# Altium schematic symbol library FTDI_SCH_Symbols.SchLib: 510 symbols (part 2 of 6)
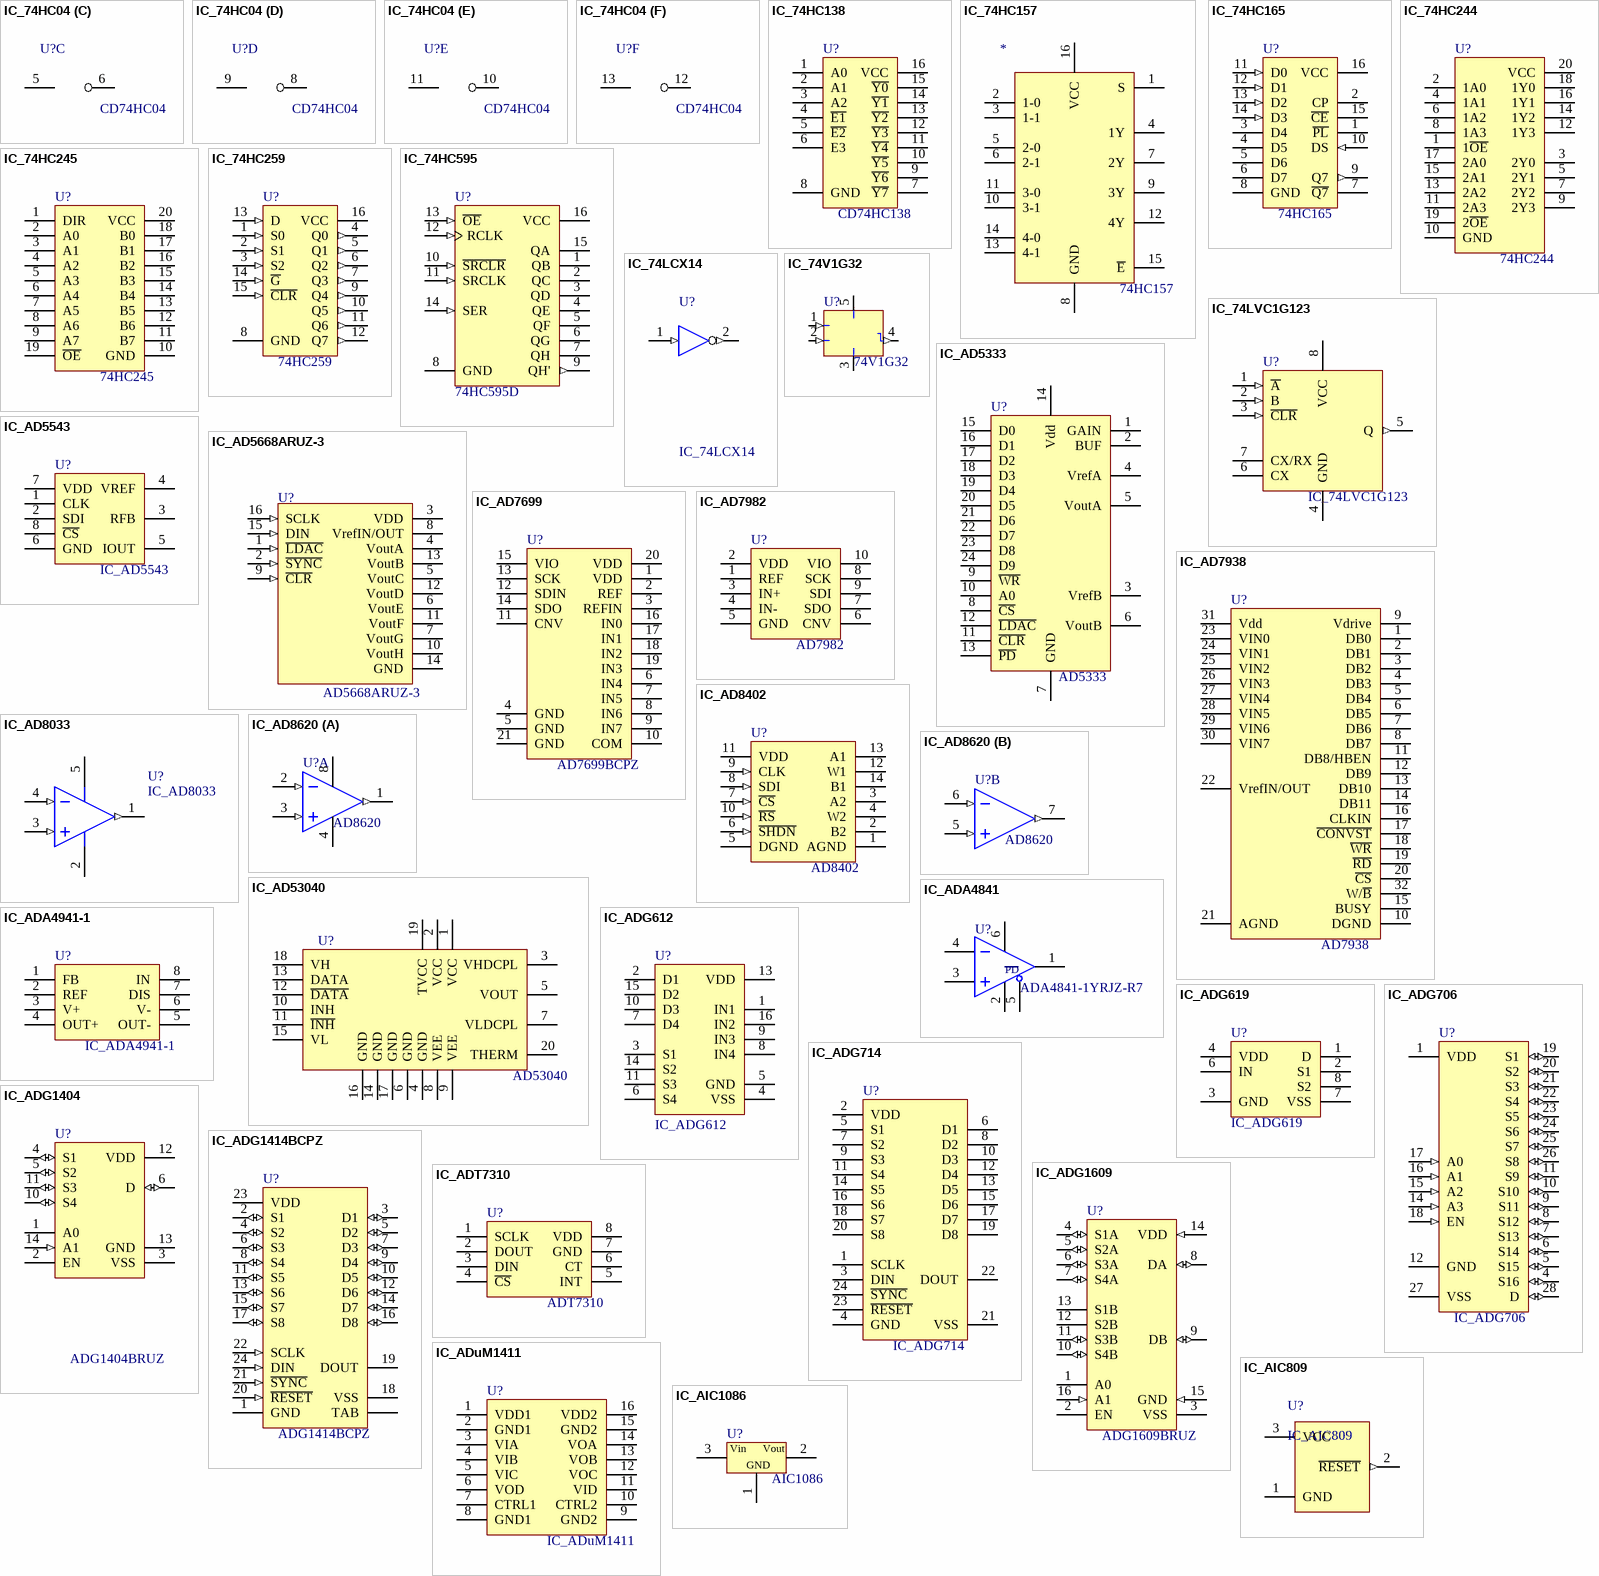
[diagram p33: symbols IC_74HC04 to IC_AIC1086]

## IC_ADG1404
designator U?, comment ADG1404BRUZ
1.5 Ohm On Resistance,  ±15 V/12 V/±5 V, 4:1, iCMOS Multiplexer
footprint TSOP65P640X110-14N (TSOP, 14-Leads, Body 5.1x4.5mm (max), Pitch 0.65mm, IPC Medium Density)
pins: 1 A0 (power), 2 EN, 3 VSS, 4 S1 (io), 5 S2 (io), 6 D (io), 7 NC (io) hidden, 8 NC (io) hidden, 9 NC (io) hidden, 10 S4 (io), 11 S3 (io), 12 VDD (power), 13 GND, 14 A1 (in)

## IC_ADG1414BCPZ
designator U?, comment ADG1414BCPZ
9.5 Ohm RON ±15 V/+12 V/±5 V iCMOS Serially-Controlled Octal SPST Switches
footprint QFN50P400X400X100-24N (QFN, 24-Leads, Body 4.1x4.1mm (max), Pitch 0.50mm, IPC Medium Density)
pins: 1 GND (power), 2 S1 (io), 3 D1 (io), 4 S2 (io), 5 D2 (io), 6 S3 (io), 7 D3 (io), 8 S4 (io), 9 D4 (io), 10 D5 (io), 11 S5 (io), 12 D6 (io), 13 S6 (io), 14 D7 (io), 15 S7 (io), 16 D8 (io), 17 S8 (io), 18 VSS (power), 19 DOUT (oc), 20 ~{RESET} (in), 21 ~{SYNC} (in), 22 SCLK (in), 23 VDD (power), 24 DIN (in), 25 TAB (power)

## IC_ADG1609
designator U?, comment ADG1609BRUZ
4.5 Ohm RON, 4-/8-Channel  ±5 V,+12 V, +5 V, and +3.3 V Multiplexers
footprint TSSOP65P640X110_HS-16N (TSOP, 16-Leads, Body 5.1x4.5mm (max), Pitch 0.65mm, IPC Medium Density)
pins: 1 A0 (power), 2 EN, 3 VSS, 4 S1A (io), 5 S2A (io), 6 S3A (io), 7 S4A (io), 8 DA (io), 9 DB (io), 10 S4B (io), 11 S3B (io), 12 S2B (power), 13 S1B, 14 VDD (in), 15 GND (in), 16 A1 (in)

## IC_ADT7310
designator U?, comment ADT7310
IC TEMP SENS 16B DGTL SPI 8SOIC; Manufacturer: Analog Devices Inc; ManufacturerPartNo: ADT7310TRZ-REEL7
signal-integrity model Connector
footprint SOIC127P600X300-8N (SOIC, 8-Leads, Body 4.9x3.9mm (max), Pitch 1.27mm, IPC Medium Density)
pins: 1 SCLK, 2 DOUT, 3 DIN, 4 ~{CS}, 5 INT, 6 CT, 7 GND, 8 VDD

## IC_ADuM1411
designator U?
Quad-Channel Digital Isolator
footprint SOICW-16_N (SOIC-Wide, 16-Leads, Body 12.8x7.5mm, Pitch 1.27mm, IPC Medium Density)
pins: 1 VDD1, 2 GND1, 3 VIA, 4 VIB, 5 VIC, 6 VOD, 7 CTRL1, 8 GND1, 9 GND2, 10 CTRL2, 11 VID, 12 VOC, 13 VOB, 14 VOA, 15 GND2, 16 VDD2

## IC_AIC809
designator U?
3-Pin Microprocessor Reset Circuit; Analog Integrations Corporation
footprint SOT23-3AL (SOT23 SMT Package)
pins: 1 GND (power), 2 ~{RESET} (out), 3 VCC (power)

## IC_AIC1086
designator U?, comment AIC1086
1.5A Low Dropout Positive Voltage Regulator
footprint TO252P990X238-3N (D-PAK, 3-Pads, Body 6.2x6.7mm (max), IPC Medium Density)
footprint SOT223P700X180-4N (SOT223, 4-Leads, Body 6.7x7.3mm (max), Pitch 2.30mm, IPC Medium Density)
pins: 1 GND (power), 2 Vout (power), 3 Vin (power)

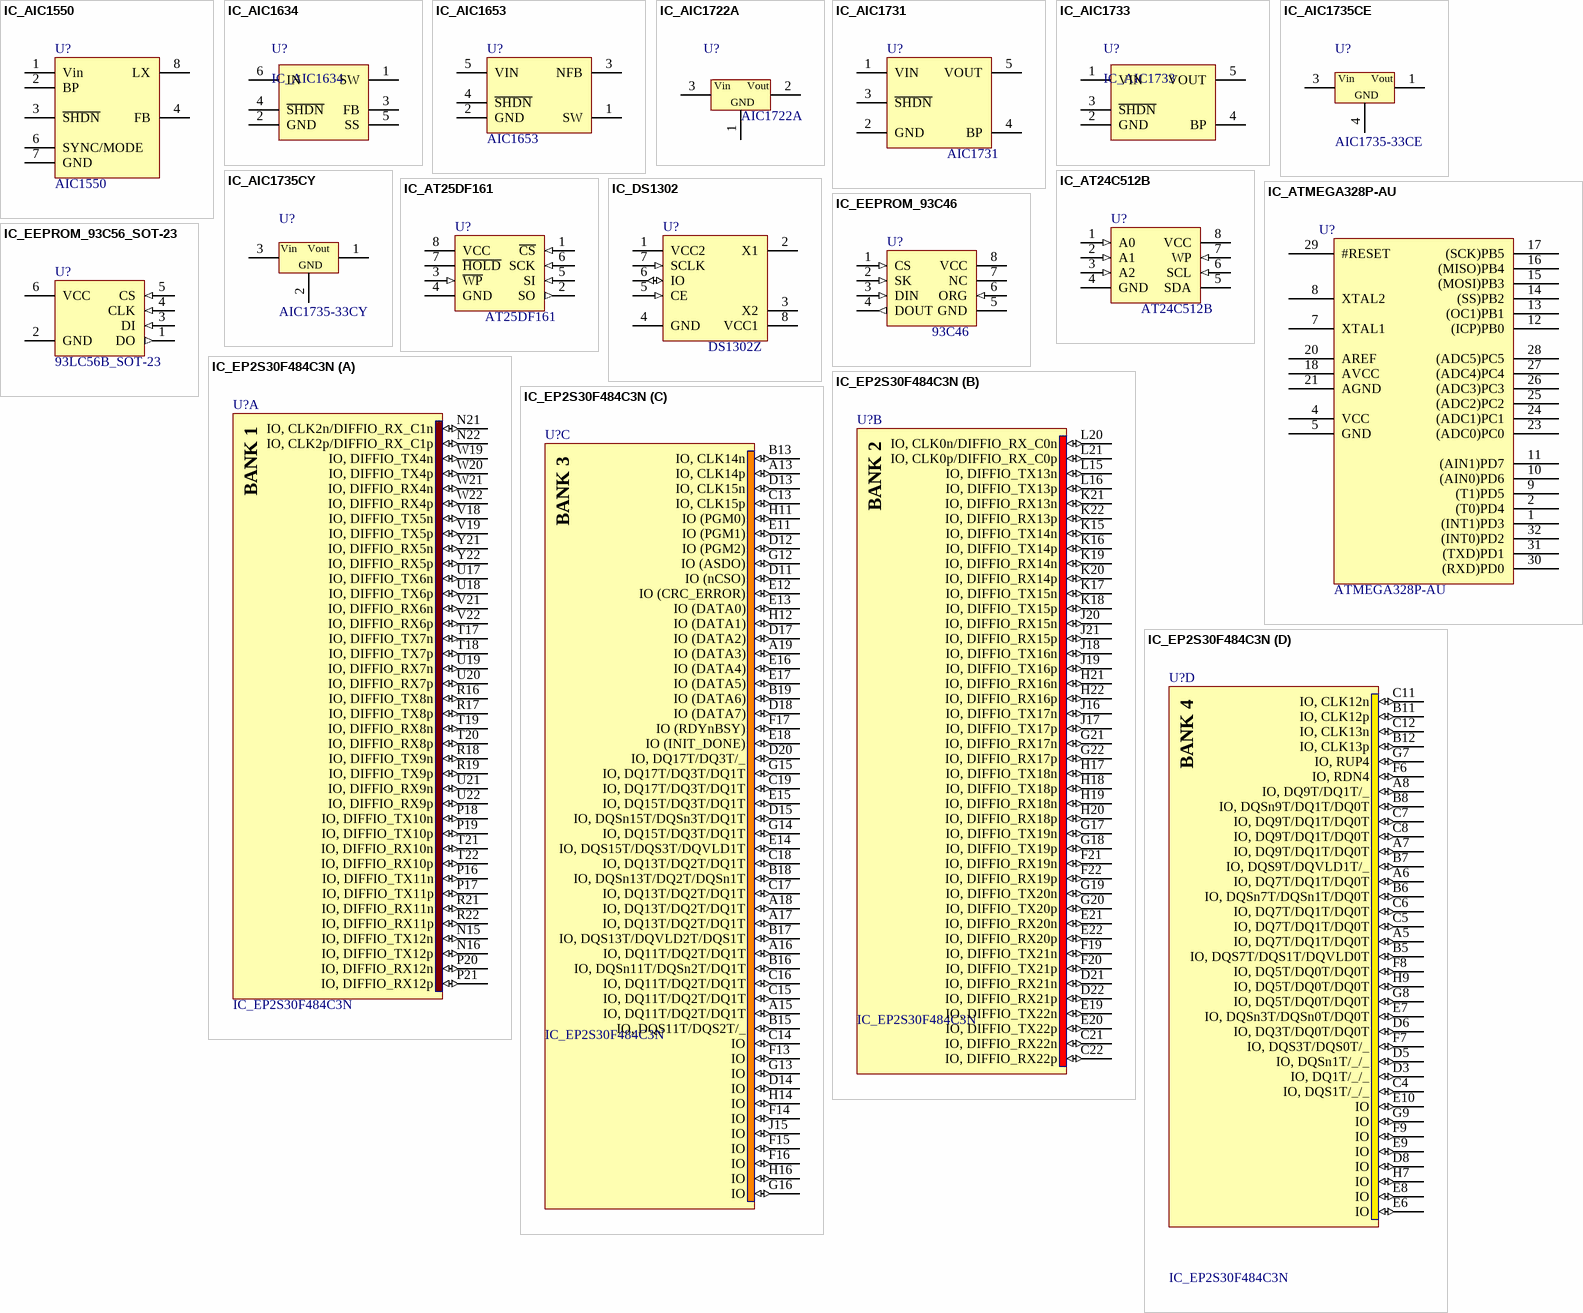
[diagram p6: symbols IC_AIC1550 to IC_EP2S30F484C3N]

## IC_AIC1550
designator U?, comment AIC1550
Low-Noise Synchronous PWM Step-Down  DC/DC Converter
footprint MSOP-08
pins: 1 Vin, 2 BP, 3 ~{SHDN}, 4 FB, 5 RT hidden, 6 SYNC/MODE, 7 GND, 8 LX

## IC_AIC1634
designator U?
1.4MHz Current-Mode, PWM Step-Up Converter
footprint SOT23-6N (SOT23, 6-Leads, Body 3.0x3.0mm (max), Pitch 0.95mm, IPC Medium Density)
pins: 1 SW, 2 GND, 3 FB, 4 ~{SHDN}, 5 SS, 6 IN

## IC_AIC1653
designator U?, comment AIC1653
Micropower Inverting DC/DC Converter in SOT-23-5
footprint SOT23-5AL (SOT23, 5-Leads, Body 2.9x1.6mm, Pitch 0.95mm, Lead Span 2.8mm)
pins: 1 SW, 2 GND, 3 NFB, 4 ~{SHDN}, 5 VIN

## IC_AIC1722A
designator U?, comment AIC1722A
300mA Low Dropout Linear Voltage Regulator; Analog Integration Corporation
footprint SOT23-3AL (SOT23 SMT Package)
pins: 1 GND (power), 2 VOUT (power), 3 VIN (power)

## IC_AIC1731
designator U?, comment AIC1731
300mA, Low Dropout Linear Regulator  with Shutdown
footprint SOT23-5AL (SOT23, 5-Leads, Body 2.9x1.6mm, Pitch 0.95mm, Lead Span 2.8mm)
pins: 1 VIN, 2 GND, 3 ~{SHDN}, 4 BP, 5 VOUT

## IC_AIC1733
designator U?
500mA, Low Dropout Linear Regulator  with Shutdown
footprint SOT23-5AL (SOT23, 5-Leads, Body 2.9x1.6mm, Pitch 0.95mm, Lead Span 2.8mm)
pins: 1 VIN, 2 GND, 3 ~{SHDN}, 4 BP, 5 VOUT

## IC_AIC1735CE
designator U?, comment AIC1735-33CE
0.5A; Vlotage Regulator; TO252
footprint TO252P990X238-3N (D-PAK, 3-Pads, Body 6.2x6.7mm (max), IPC Medium Density)
pins: 1 Vout (power), 3 Vin (power), 4 GND (power)

## IC_AIC1735CY
designator U?, comment AIC1735-33CY
0.5A; Vlotage Regulator; SOT223
footprint SOT223P700X180-4N (SOT223, 4-Leads, Body 6.7x7.3mm (max), Pitch 2.30mm, IPC Medium Density)
pins: 1 Vout (power), 2 GND (power), 3 Vin (power), 4 GND (power) hidden to GND

## IC_AT24C512B
designator U?, comment AT24C512B
Two-wire Serial  EEPROM  512K (65,536 x 8)
pins: 1 A0 (in), 2 A1 (in), 3 A2 (in), 4 GND (power), 5 SDA (oc), 6 SCL (in), 7 WP (in), 8 VCC (power)

## IC_AT25DF161
designator U?, comment AT25DF161
16-Megabit  2.3V or 2.7V  Minimum  SPI Serial Flash  Memory; Atmel
footprint SO-8N (8-Pin Small Outline Integrated Circuit 1.27 mm Pitch, IPC Medium Density)
pins: 1 ~{CS} (in), 2 SO (out), 3 ~{WP} (in), 4 GND (power), 5 SI (in), 6 SCK (in), 7 ~{HOLD}, 8 VCC (power)

## IC_ATMEGA328P-AU
designator U?, comment ATMEGA328P-AU
pins: 1 (INT1)PD3, 2 (T0)PD4, 4 VCC, 5 GND, 7 XTAL1, 8 XTAL2, 9 (T1)PD5, 10 (AIN0)PD6, 11 (AIN1)PD7, 12 (ICP)PB0, 13 (OC1)PB1, 14 (SS)PB2, 15 (MOSI)PB3, 16 (MISO)PB4, 17 (SCK)PB5, 18 AVCC, 20 AREF, 21 AGND, 23 (ADC0)PC0, 24 (ADC1)PC1, 25 (ADC2)PC2, 26 (ADC3)PC3, 27 (ADC4)PC4, 28 (ADC5)PC5, 29 #RESET, 30 (RXD)PD0, 31 (TXD)PD1, 32 (INT0)PD2

## IC_DS1302
designator U?, comment DS1302Z
Trickle-Charge Timekeeping Chip
footprint SO-8N (8-Pin Small Outline Integrated Circuit 1.27 mm Pitch, IPC Medium Density)
pins: 1 VCC2 (power), 2 X1, 3 X2, 4 GND (power), 5 CE (in), 6 IO (io), 7 SCLK (in), 8 VCC1 (power)

## IC_EEPROM_93C46
designator U?, comment 93C46
Serial interface EEPROM
footprint SO-8_N (8-Pin Small Outline Integrated Circuit 1.27 mm Pitch, IPC Medium Density)
footprint TSSOP-8 (Shrink Small Outline; 8 Leads; Body Width 4.4 mm; Pitch 0.65 mm)
pins: 1 CS (in), 2 SK (in), 3 DIN (in), 4 DOUT (out), 5 GND (power), 6 ORG (in), 7 NC, 8 VCC (power)

## IC_EEPROM_93C56_SOT-23
designator U?, comment 93LC56B_SOT-23
Serial interface EEPROM in SOT-23 package
footprint SOT23-6N (SOT23, 6-Leads, Body 3.0x3.0mm (max), Pitch 0.95mm, IPC Medium Density)
pins: 1 DO (out), 2 GND (power), 3 DI (in), 4 CLK (in), 5 CS (in), 6 VCC (power)

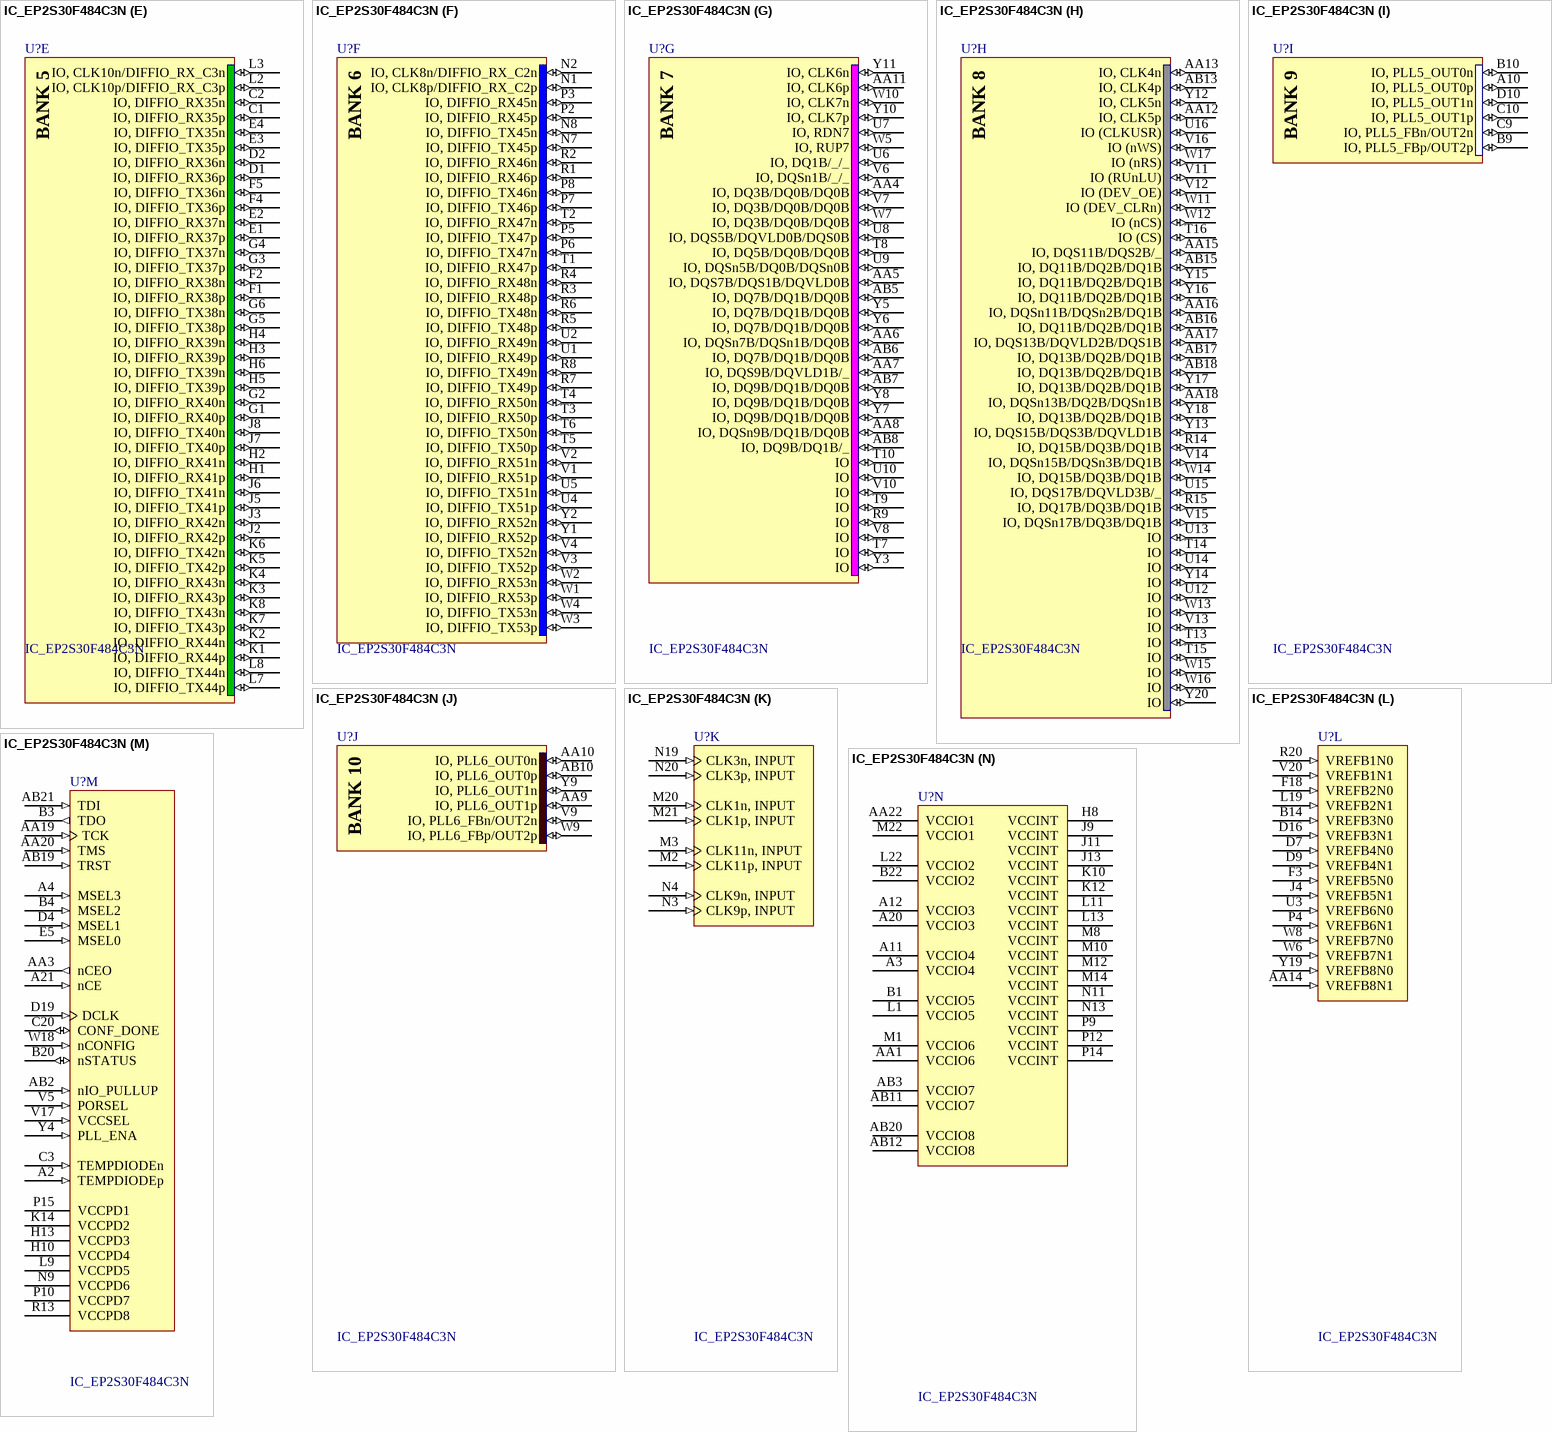
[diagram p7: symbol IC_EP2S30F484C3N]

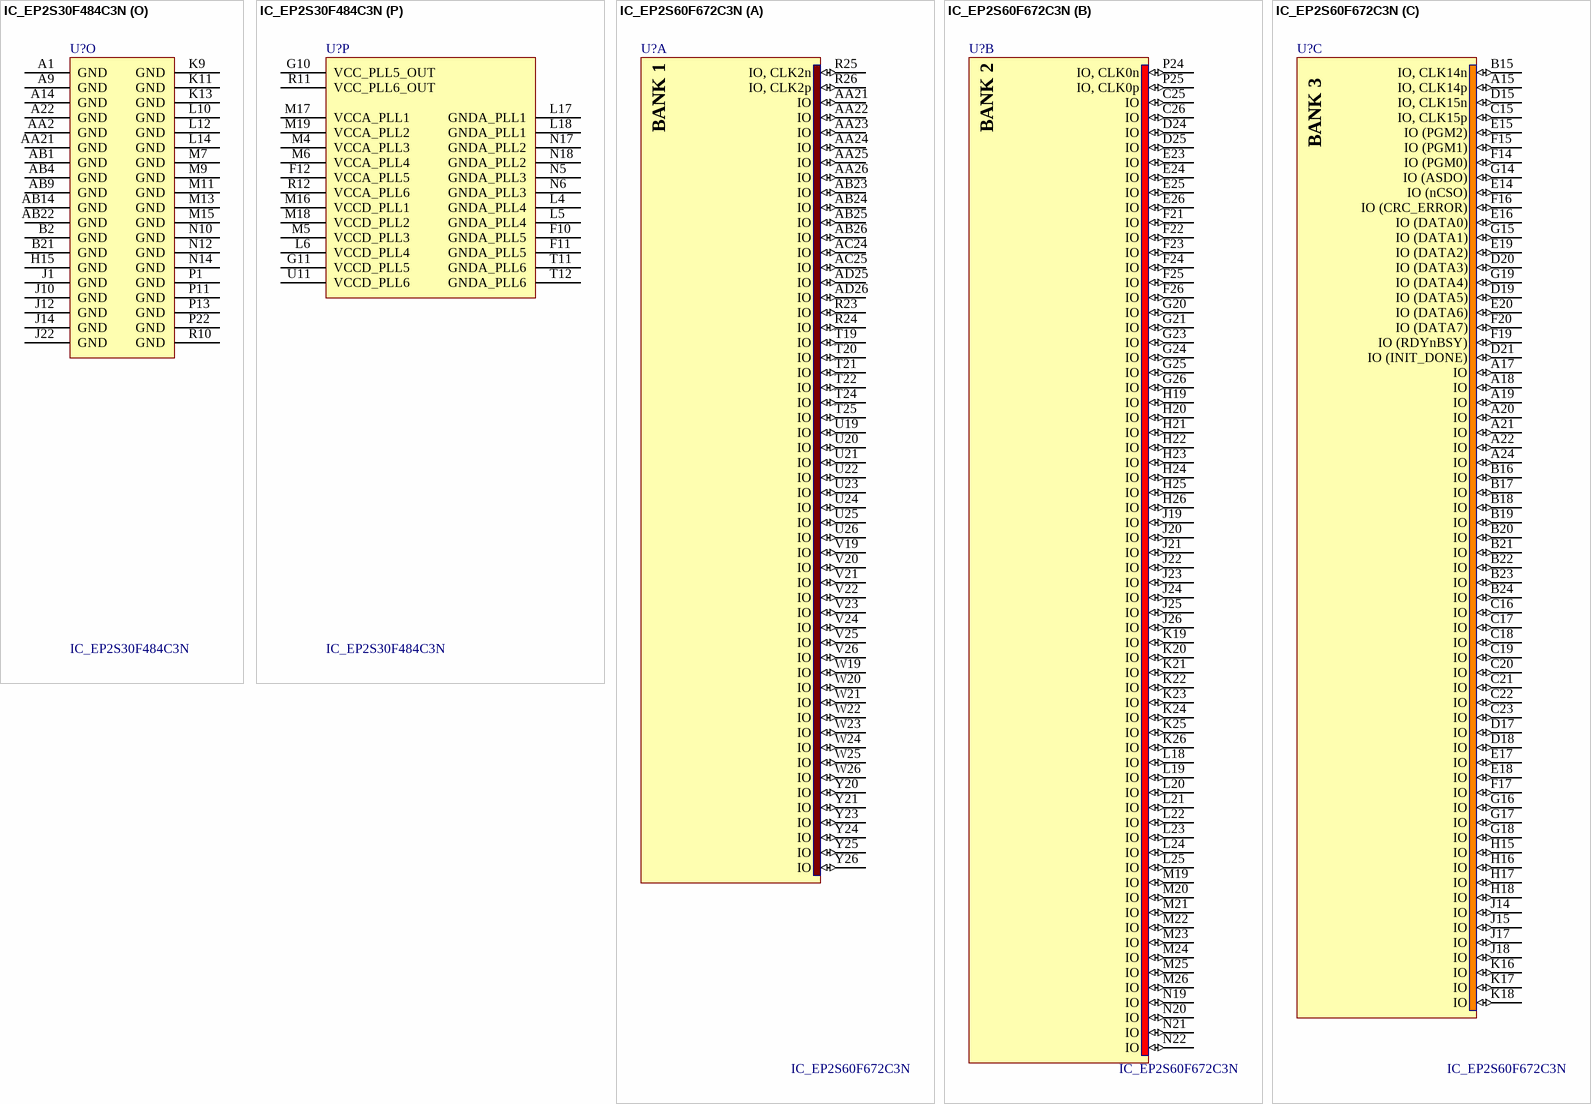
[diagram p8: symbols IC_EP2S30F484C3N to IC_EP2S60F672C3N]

## IC_EP2S30F484C3N
designator U?
Stratix II 1.2V FPGA, 334 I/Os, 484-Pin FineLine BGA, Speed Grade 3, Commercial Grade, Pb-Free; Note: DQS signal pins in banks 3, 4, 7 & 8 named according to DQ bus modes. "/" separates each mode. ie. Mode x4, Mode x8/x9, Mode x16/x18.
footprint FBGA484 (BGA, 484-Leads, Body 23x23mm, Pitch 1mm)
3D model EP2S30-FBGA484T (PCB3D Model)
part A pins: N15 IO, DIFFIO_TX12n (io), N16 IO, DIFFIO_TX12p (io), N21 IO, CLK2n/DIFFIO_RX_C1n (io), N22 IO, CLK2p/DIFFIO_RX_C1p (io), P16 IO, DIFFIO_TX11n (io), P17 IO, DIFFIO_TX11p (io), P18 IO, DIFFIO_TX10n (io), P19 IO, DIFFIO_TX10p (io), P20 IO, DIFFIO_RX12n (io), P21 IO, DIFFIO_RX12p (io), R16 IO, DIFFIO_TX8n (io), R17 IO, DIFFIO_TX8p (io), R18 IO, DIFFIO_TX9n (io), R19 IO, DIFFIO_TX9p (io), R21 IO, DIFFIO_RX11n (io), R22 IO, DIFFIO_RX11p (io), T17 IO, DIFFIO_TX7n (io), T18 IO, DIFFIO_TX7p (io), T19 IO, DIFFIO_RX8n (io), T20 IO, DIFFIO_RX8p (io), T21 IO, DIFFIO_RX10n (io), T22 IO, DIFFIO_RX10p (io), U17 IO, DIFFIO_TX6n (io), U18 IO, DIFFIO_TX6p (io), U19 IO, DIFFIO_RX7n (io), U20 IO, DIFFIO_RX7p (io), U21 IO, DIFFIO_RX9n (io), U22 IO, DIFFIO_RX9p (io), V18 IO, DIFFIO_TX5n (io), V19 IO, DIFFIO_TX5p (io), V21 IO, DIFFIO_RX6n (io), V22 IO, DIFFIO_RX6p (io), W19 IO, DIFFIO_TX4n (io), W20 IO, DIFFIO_TX4p (io), W21 IO, DIFFIO_RX4n (io), W22 IO, DIFFIO_RX4p (io), Y21 IO, DIFFIO_RX5n (io), Y22 IO, DIFFIO_RX5p (io)
part B pins: C21 IO, DIFFIO_RX22n (io), C22 IO, DIFFIO_RX22p (io), D21 IO, DIFFIO_RX21n (io), D22 IO, DIFFIO_RX21p (io), E19 IO, DIFFIO_TX22n (io), E20 IO, DIFFIO_TX22p (io), E21 IO, DIFFIO_RX20n (io), E22 IO, DIFFIO_RX20p (io), F19 IO, DIFFIO_TX21n (io), F20 IO, DIFFIO_TX21p (io), F21 IO, DIFFIO_RX19n (io), F22 IO, DIFFIO_RX19p (io), G17 IO, DIFFIO_TX19n (io), G18 IO, DIFFIO_TX19p (io), G19 IO, DIFFIO_TX20n (io), G20 IO, DIFFIO_TX20p (io), G21 IO, DIFFIO_RX17n (io), G22 IO, DIFFIO_RX17p (io), H17 IO, DIFFIO_TX18n (io), H18 IO, DIFFIO_TX18p (io), H19 IO, DIFFIO_RX18n (io), H20 IO, DIFFIO_RX18p (io), H21 IO, DIFFIO_RX16n (io), H22 IO, DIFFIO_RX16p (io), J16 IO, DIFFIO_TX17n (io), J17 IO, DIFFIO_TX17p (io), J18 IO, DIFFIO_TX16n (io), J19 IO, DIFFIO_TX16p (io), J20 IO, DIFFIO_RX15n (io), J21 IO, DIFFIO_RX15p (io), K15 IO, DIFFIO_TX14n (io), K16 IO, DIFFIO_TX14p (io), K17 IO, DIFFIO_TX15n (io), K18 IO, DIFFIO_TX15p (io), K19 IO, DIFFIO_RX14n (io), K20 IO, DIFFIO_RX14p (io), K21 IO, DIFFIO_RX13n (io), K22 IO, DIFFIO_RX13p (io), L15 IO, DIFFIO_TX13n (io), L16 IO, DIFFIO_TX13p (io), L20 IO, CLK0n/DIFFIO_RX_C0n (io), L21 IO, CLK0p/DIFFIO_RX_C0p (io)
part C pins: A13 IO, CLK14p (io), A15 IO, DQ11T/DQ2T/DQ1T (io), A16 IO, DQ11T/DQ2T/DQ1T (io), A17 IO, DQ13T/DQ2T/DQ1T (io), A18 IO, DQ13T/DQ2T/DQ1T (io), A19 IO (DATA3) (io), B13 IO, CLK14n (io), B15 IO, DQS11T/DQS2T/_ (io), B16 IO, DQSn11T/DQSn2T/DQ1T (io), B17 IO, DQS13T/DQVLD2T/DQS1T (io), B18 IO, DQSn13T/DQ2T/DQSn1T (io), B19 IO (DATA6) (io), C13 IO, CLK15p (io), C14 IO (io), C15 IO, DQ11T/DQ2T/DQ1T (io), C16 IO, DQ11T/DQ2T/DQ1T (io), C17 IO, DQ13T/DQ2T/DQ1T (io), C18 IO, DQ13T/DQ2T/DQ1T (io), C19 IO, DQ17T/DQ3T/DQ1T (io), D11 IO (nCSO) (io), D12 IO (PGM2) (io), D13 IO, CLK15n (io), D14 IO (io), D15 IO, DQSn15T/DQSn3T/DQ1T (io), D17 IO (DATA2) (io), D18 IO (DATA7) (io), D20 IO, DQ17T/DQ3T/_ (io), E11 IO (PGM1) (io), E12 IO (CRC_ERROR) (io), E13 IO (DATA0) (io), E14 IO, DQS15T/DQS3T/DQVLD1T (io), E15 IO, DQ15T/DQ3T/DQ1T (io), E16 IO (DATA4) (io), E17 IO (DATA5) (io), E18 IO (INIT_DONE) (io), F13 IO (io), F14 IO (io), F15 IO (io), F16 IO (io), F17 IO (RDYnBSY) (io), G12 IO (ASDO) (io), G13 IO (io), G14 IO, DQ15T/DQ3T/DQ1T (io), G15 IO, DQ17T/DQ3T/DQ1T (io), G16 IO (io), H11 IO (PGM0) (io), H12 IO (DATA1) (io), H14 IO (io), H16 IO (io), J15 IO (io)
part D pins: A5 IO, DQ7T/DQ1T/DQ0T (io), A6 IO, DQ7T/DQ1T/DQ0T (io), A7 IO, DQ9T/DQ1T/DQ0T (io), A8 IO, DQ9T/DQ1T/_ (io), B5 IO, DQS7T/DQS1T/DQVLD0T (io), B6 IO, DQSn7T/DQSn1T/DQ0T (io), B7 IO, DQS9T/DQVLD1T/_ (io), B8 IO, DQSn9T/DQ1T/DQ0T (io), B11 IO, CLK12p (io), B12 IO, CLK13p (io), C4 IO, DQS1T/_/_ (io), C5 IO, DQ7T/DQ1T/DQ0T (io), C6 IO, DQ7T/DQ1T/DQ0T (io), C7 IO, DQ9T/DQ1T/DQ0T (io), C8 IO, DQ9T/DQ1T/DQ0T (io), C11 IO, CLK12n (io), C12 IO, CLK13n (io), D3 IO, DQ1T/_/_ (io), D5 IO, DQSn1T/_/_ (io), D6 IO, DQ3T/DQ0T/DQ0T (io), D8 IO (io), E6 IO (io), E7 IO, DQSn3T/DQSn0T/DQ0T (io), E8 IO (io), E9 IO (io), E10 IO (io), F6 IO, RDN4 (io), F7 IO, DQS3T/DQS0T/_ (io), F8 IO, DQ5T/DQ0T/DQ0T (io), F9 IO (io), G7 IO, RUP4 (io), G8 IO, DQ5T/DQ0T/DQ0T (io), G9 IO (io), H7 IO (io), H9 IO, DQ5T/DQ0T/DQ0T (io)
part E pins: C1 IO, DIFFIO_RX35p (io), C2 IO, DIFFIO_RX35n (io), D1 IO, DIFFIO_RX36p (io), D2 IO, DIFFIO_RX36n (io), E1 IO, DIFFIO_RX37p (io), E2 IO, DIFFIO_RX37n (io), E3 IO, DIFFIO_TX35p (io), E4 IO, DIFFIO_TX35n (io), F1 IO, DIFFIO_RX38p (io), F2 IO, DIFFIO_RX38n (io), F4 IO, DIFFIO_TX36p (io), F5 IO, DIFFIO_TX36n (io), G1 IO, DIFFIO_RX40p (io), G2 IO, DIFFIO_RX40n (io), G3 IO, DIFFIO_TX37p (io), G4 IO, DIFFIO_TX37n (io), G5 IO, DIFFIO_TX38p (io), G6 IO, DIFFIO_TX38n (io), H1 IO, DIFFIO_RX41p (io), H2 IO, DIFFIO_RX41n (io), H3 IO, DIFFIO_RX39p (io), H4 IO, DIFFIO_RX39n (io), H5 IO, DIFFIO_TX39p (io), H6 IO, DIFFIO_TX39n (io), J2 IO, DIFFIO_RX42p (io), J3 IO, DIFFIO_RX42n (io), J5 IO, DIFFIO_TX41p (io), J6 IO, DIFFIO_TX41n (io), J7 IO, DIFFIO_TX40p (io), J8 IO, DIFFIO_TX40n (io), K1 IO, DIFFIO_RX44p (io), K2 IO, DIFFIO_RX44n (io), K3 IO, DIFFIO_RX43p (io), K4 IO, DIFFIO_RX43n (io), K5 IO, DIFFIO_TX42p (io), K6 IO, DIFFIO_TX42n (io), K7 IO, DIFFIO_TX43p (io), K8 IO, DIFFIO_TX43n (io), L2 IO, CLK10p/DIFFIO_RX_C3p (io), L3 IO, CLK10n/DIFFIO_RX_C3n (io), L7 IO, DIFFIO_TX44p (io), L8 IO, DIFFIO_TX44n (io)
part F pins: N1 IO, CLK8p/DIFFIO_RX_C2p (io), N2 IO, CLK8n/DIFFIO_RX_C2n (io), N7 IO, DIFFIO_TX45p (io), N8 IO, DIFFIO_TX45n (io), P2 IO, DIFFIO_RX45p (io), P3 IO, DIFFIO_RX45n (io), P5 IO, DIFFIO_TX47p (io), P6 IO, DIFFIO_TX47n (io), P7 IO, DIFFIO_TX46p (io), P8 IO, DIFFIO_TX46n (io), R1 IO, DIFFIO_RX46p (io), R2 IO, DIFFIO_RX46n (io), R3 IO, DIFFIO_RX48p (io), R4 IO, DIFFIO_RX48n (io), R5 IO, DIFFIO_TX48p (io), R6 IO, DIFFIO_TX48n (io), R7 IO, DIFFIO_TX49p (io), R8 IO, DIFFIO_TX49n (io), T1 IO, DIFFIO_RX47p (io), T2 IO, DIFFIO_RX47n (io), T3 IO, DIFFIO_RX50p (io), T4 IO, DIFFIO_RX50n (io), T5 IO, DIFFIO_TX50p (io), T6 IO, DIFFIO_TX50n (io), U1 IO, DIFFIO_RX49p (io), U2 IO, DIFFIO_RX49n (io), U4 IO, DIFFIO_TX51p (io), U5 IO, DIFFIO_TX51n (io), V1 IO, DIFFIO_RX51p (io), V2 IO, DIFFIO_RX51n (io), V3 IO, DIFFIO_TX52p (io), V4 IO, DIFFIO_TX52n (io), W1 IO, DIFFIO_RX53p (io), W2 IO, DIFFIO_RX53n (io), W3 IO, DIFFIO_TX53p (io), W4 IO, DIFFIO_TX53n (io), Y1 IO, DIFFIO_RX52p (io), Y2 IO, DIFFIO_RX52n (io)
part G pins: AA4 IO, DQ3B/DQ0B/DQ0B (io), AA5 IO, DQS7B/DQS1B/DQVLD0B (io), AA6 IO, DQSn7B/DQSn1B/DQ0B (io), AA7 IO, DQS9B/DQVLD1B/_ (io), AA8 IO, DQSn9B/DQ1B/DQ0B (io), AA11 IO, CLK6p (io), AB5 IO, DQ7B/DQ1B/DQ0B (io), AB6 IO, DQ7B/DQ1B/DQ0B (io), AB7 IO, DQ9B/DQ1B/DQ0B (io), AB8 IO, DQ9B/DQ1B/_ (io), R9 IO (io), T7 IO (io), T8 IO, DQ5B/DQ0B/DQ0B (io), T9 IO (io), T10 IO (io), U6 IO, DQ1B/_/_ (io), U7 IO, RDN7 (io), U8 IO, DQS5B/DQVLD0B/DQS0B (io), U9 IO, DQSn5B/DQ0B/DQSn0B (io), U10 IO (io), V6 IO, DQSn1B/_/_ (io), V7 IO, DQ3B/DQ0B/DQ0B (io), V8 IO (io), V10 IO (io), W5 IO, RUP7 (io), W7 IO, DQ3B/DQ0B/DQ0B (io), W10 IO, CLK7n (io), Y3 IO (io), Y5 IO, DQ7B/DQ1B/DQ0B (io), Y6 IO, DQ7B/DQ1B/DQ0B (io), Y7 IO, DQ9B/DQ1B/DQ0B (io), Y8 IO, DQ9B/DQ1B/DQ0B (io), Y10 IO, CLK7p (io), Y11 IO, CLK6n (io)
part H pins: AA12 IO, CLK5p (io), AA13 IO, CLK4n (io), AA15 IO, DQS11B/DQS2B/_ (io), AA16 IO, DQSn11B/DQSn2B/DQ1B (io), AA17 IO, DQS13B/DQVLD2B/DQS1B (io), AA18 IO, DQSn13B/DQ2B/DQSn1B (io), AB13 IO, CLK4p (io), AB15 IO, DQ11B/DQ2B/DQ1B (io), AB16 IO, DQ11B/DQ2B/DQ1B (io), AB17 IO, DQ13B/DQ2B/DQ1B (io), AB18 IO, DQ13B/DQ2B/DQ1B (io), R14 IO, DQ15B/DQ3B/DQ1B (io), R15 IO, DQ17B/DQ3B/DQ1B (io), T13 IO (io), T14 IO (io), T15 IO (io), T16 IO (CS) (io), U12 IO (io), U13 IO (io), U14 IO (io), U15 IO, DQS17B/DQVLD3B/_ (io), U16 IO (CLKUSR) (io), V11 IO (RUnLU) (io), V12 IO (DEV_OE) (io), V13 IO (io), V14 IO, DQSn15B/DQSn3B/DQ1B (io), V15 IO, DQSn17B/DQ3B/DQ1B (io), V16 IO (nWS) (io), W11 IO (DEV_CLRn) (io), W12 IO (nCS) (io), W13 IO (io), W14 IO, DQ15B/DQ3B/DQ1B (io), W15 IO (io), W16 IO (io), W17 IO (nRS) (io), Y12 IO, CLK5n (io), Y13 IO, DQS15B/DQS3B/DQVLD1B (io), Y14 IO (io), Y15 IO, DQ11B/DQ2B/DQ1B (io), Y16 IO, DQ11B/DQ2B/DQ1B (io), Y17 IO, DQ13B/DQ2B/DQ1B (io), Y18 IO, DQ13B/DQ2B/DQ1B (io), Y20 IO (io)
part I pins: A10 IO, PLL5_OUT0p (io), B9 IO, PLL5_FBp/OUT2p (io), B10 IO, PLL5_OUT0n (io), C9 IO, PLL5_FBn/OUT2n (io), C10 IO, PLL5_OUT1p (io), D10 IO, PLL5_OUT1n (io)
part J pins: AA9 IO, PLL6_OUT1p (io), AA10 IO, PLL6_OUT0n (io), AB10 IO, PLL6_OUT0p (io), V9 IO, PLL6_FBn/OUT2n (io), W9 IO, PLL6_FBp/OUT2p (io), Y9 IO, PLL6_OUT1n (io)
part K pins: M2 CLK11p, INPUT (in), M3 CLK11n, INPUT (in), M20 CLK1n, INPUT (in), M21 CLK1p, INPUT (in), N3 CLK9p, INPUT (in), N4 CLK9n, INPUT (in), N19 CLK3n, INPUT (in), N20 CLK3p, INPUT (in)
part L pins: AA14 VREFB8N1 (in), B14 VREFB3N0 (in), D7 VREFB4N0 (in), D9 VREFB4N1 (in), D16 VREFB3N1 (in), F3 VREFB5N0 (in), F18 VREFB2N0 (in), J4 VREFB5N1 (in), L19 VREFB2N1 (in), P4 VREFB6N1 (in), R20 VREFB1N0 (in), U3 VREFB6N0 (in), V20 VREFB1N1 (in), W6 VREFB7N1 (in), W8 VREFB7N0 (in), Y19 VREFB8N0 (in)
part M pins: A2 TEMPDIODEp (in), A4 MSEL3 (in), A21 nCE (in), AA3 nCEO (out), AA19 TCK (in), AA20 TMS (in), AB2 nIO_PULLUP (in), AB19 TRST (in), AB21 TDI (in), B3 TDO (out), B4 MSEL2 (in), B20 nSTATUS (io), C3 TEMPDIODEn (in), C20 CONF_DONE (io), D4 MSEL1 (in), D19 DCLK (in), E5 MSEL0 (in), H10 VCCPD4 (power), H13 VCCPD3 (power), K14 VCCPD2 (power), L9 VCCPD5 (power), N9 VCCPD6 (power), P10 VCCPD7 (power), P15 VCCPD1 (power), R13 VCCPD8 (power), V5 PORSEL (in), V17 VCCSEL (in), W18 nCONFIG (in), Y4 PLL_ENA (in)
part N pins: A3 VCCIO4 (power), A11 VCCIO4 (power), A12 VCCIO3 (power), A20 VCCIO3 (power), AA1 VCCIO6 (power), AA22 VCCIO1 (power), AB3 VCCIO7 (power), AB11 VCCIO7 (power), AB12 VCCIO8 (power), AB20 VCCIO8 (power), B1 VCCIO5 (power), B22 VCCIO2 (power), H8 VCCINT (power), J9 VCCINT (power), J11 VCCINT (power), J13 VCCINT (power), K10 VCCINT (power), K12 VCCINT (power), L1 VCCIO5 (power), L11 VCCINT (power), L13 VCCINT (power), L22 VCCIO2 (power), M1 VCCIO6 (power), M8 VCCINT (power), M10 VCCINT (power), M12 VCCINT (power), M14 VCCINT (power), M22 VCCIO1 (power), N11 VCCINT (power), N13 VCCINT (power), P9 VCCINT (power), P12 VCCINT (power), P14 VCCINT (power)
part O pins: A1 GND (power), A9 GND (power), A14 GND (power), A22 GND (power), AA2 GND (power), AA21 GND (power), AB1 GND (power), AB4 GND (power), AB9 GND (power), AB14 GND (power), AB22 GND (power), B2 GND (power), B21 GND (power), H15 GND (power), J1 GND (power), J10 GND (power), J12 GND (power), J14 GND (power), J22 GND (power), K9 GND (power), K11 GND (power), K13 GND (power), L10 GND (power), L12 GND (power), L14 GND (power), M7 GND (power), M9 GND (power), M11 GND (power), M13 GND (power), M15 GND (power), N10 GND (power), N12 GND (power), N14 GND (power), P1 GND (power), P11 GND (power), P13 GND (power), P22 GND (power), R10 GND (power)
part P pins: F10 GNDA_PLL5 (power), F11 GNDA_PLL5 (power), F12 VCCA_PLL5 (power), G10 VCC_PLL5_OUT (power), G11 VCCD_PLL5 (power), L4 GNDA_PLL4 (power), L5 GNDA_PLL4 (power), L6 VCCD_PLL4 (power), L17 GNDA_PLL1 (power), L18 GNDA_PLL1 (power), M4 VCCA_PLL3 (power), M5 VCCD_PLL3 (power), M6 VCCA_PLL4 (power), M16 VCCD_PLL1 (power), M17 VCCA_PLL1 (power), M18 VCCD_PLL2 (power), M19 VCCA_PLL2 (power), N5 GNDA_PLL3 (power), N6 GNDA_PLL3 (power), N17 GNDA_PLL2 (power), N18 GNDA_PLL2 (power), R11 VCC_PLL6_OUT (power), R12 VCCA_PLL6 (power), T11 GNDA_PLL6 (power), T12 GNDA_PLL6 (power), U11 VCCD_PLL6 (power)

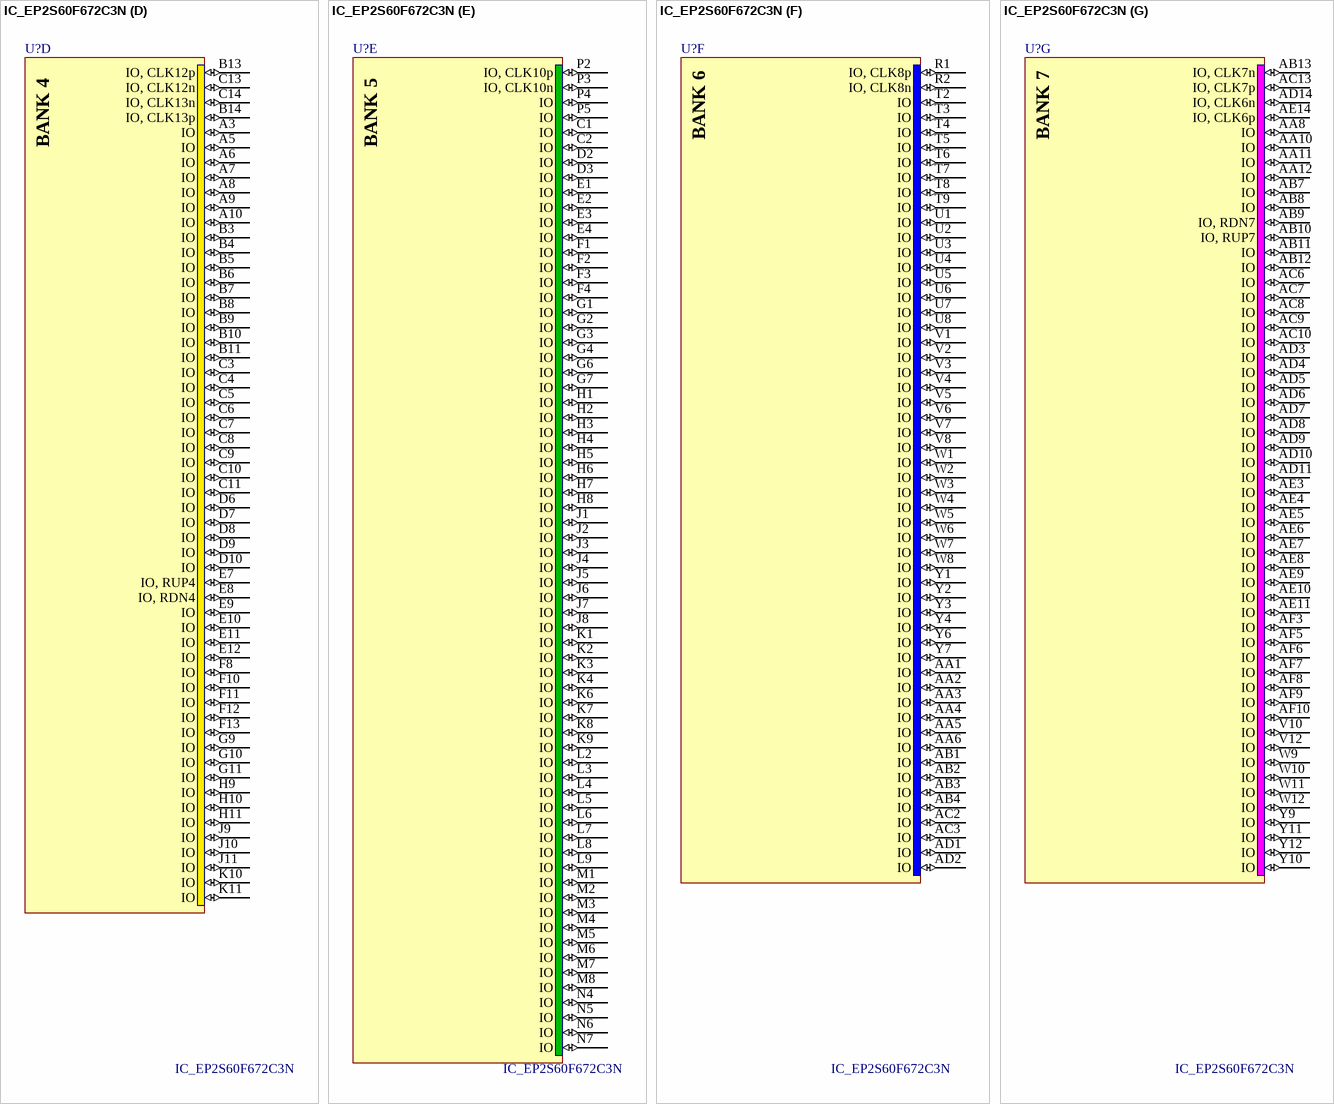
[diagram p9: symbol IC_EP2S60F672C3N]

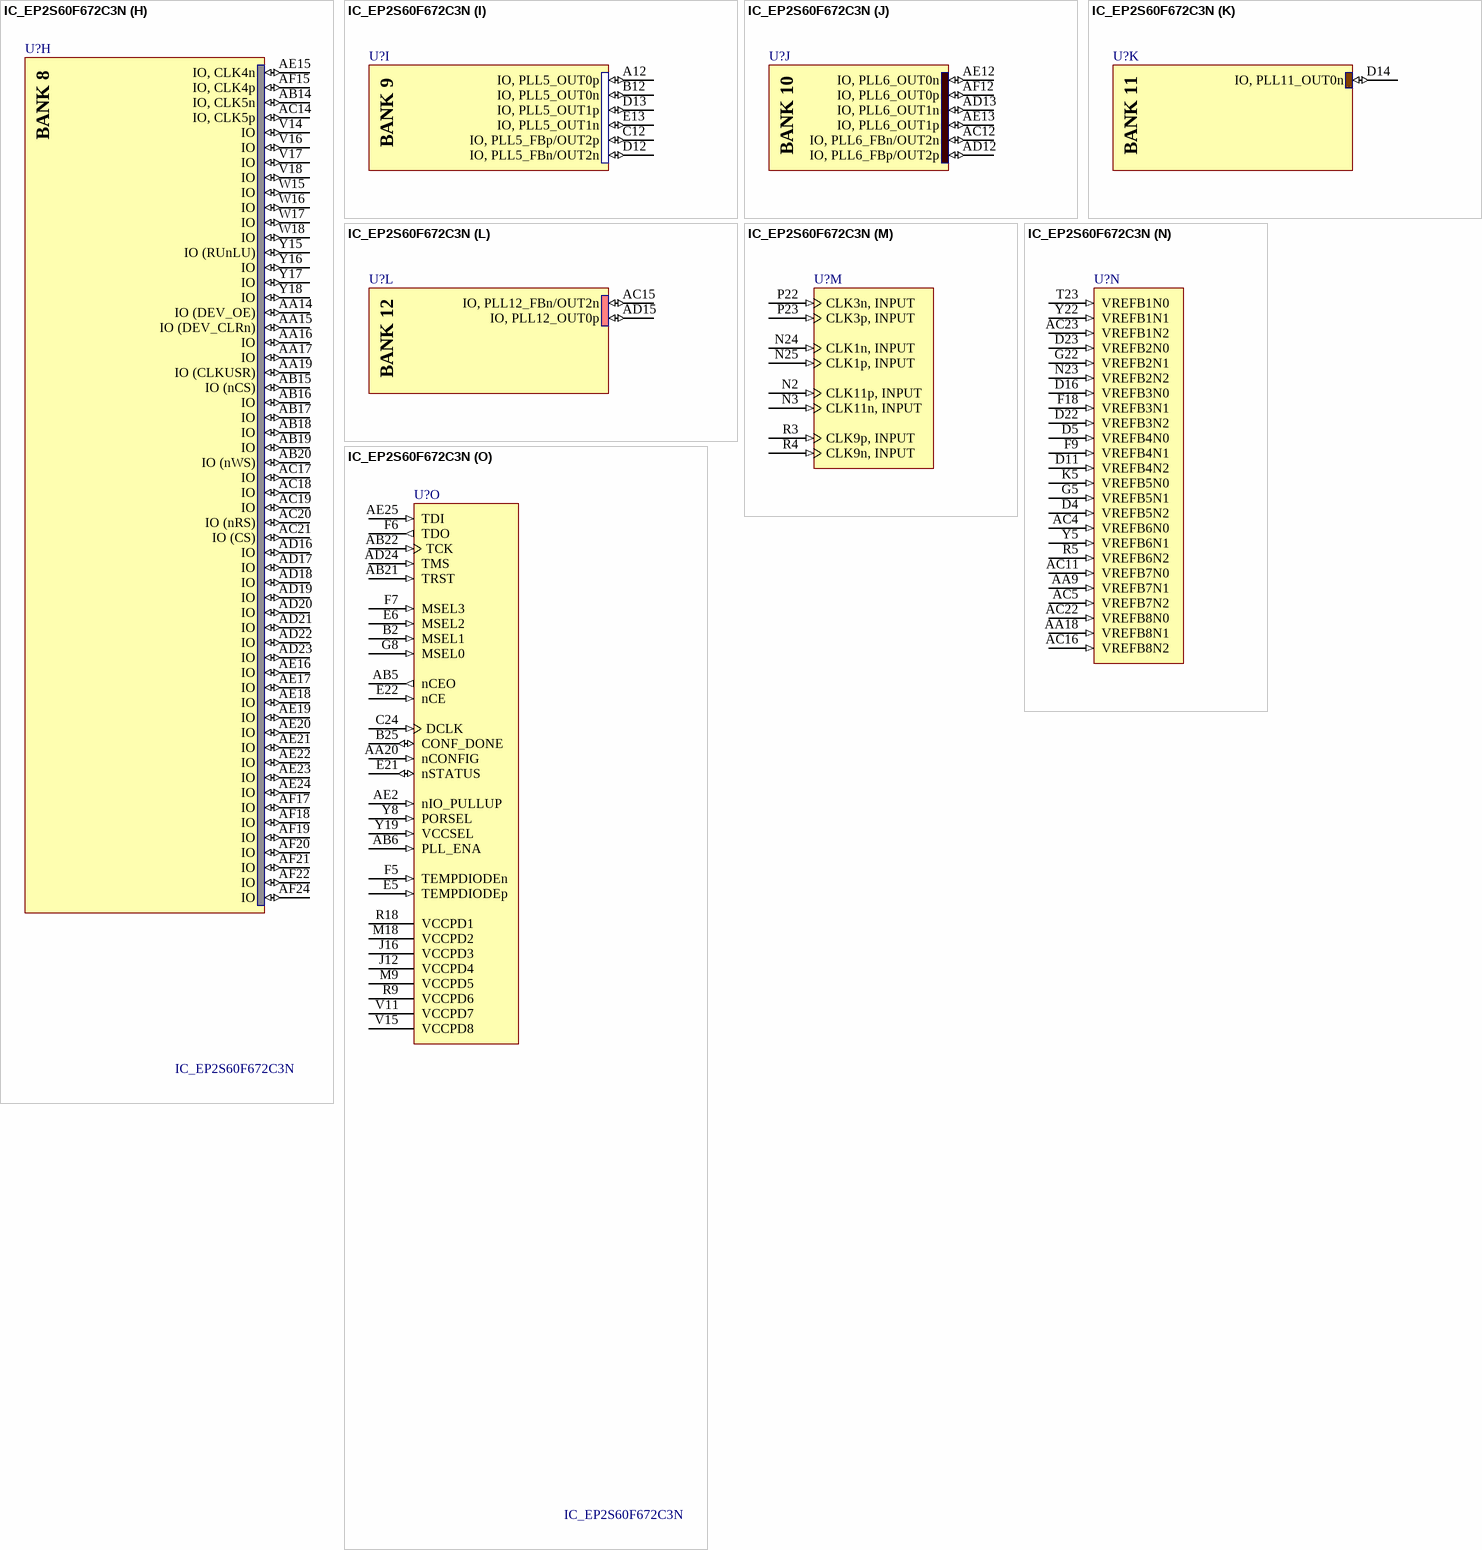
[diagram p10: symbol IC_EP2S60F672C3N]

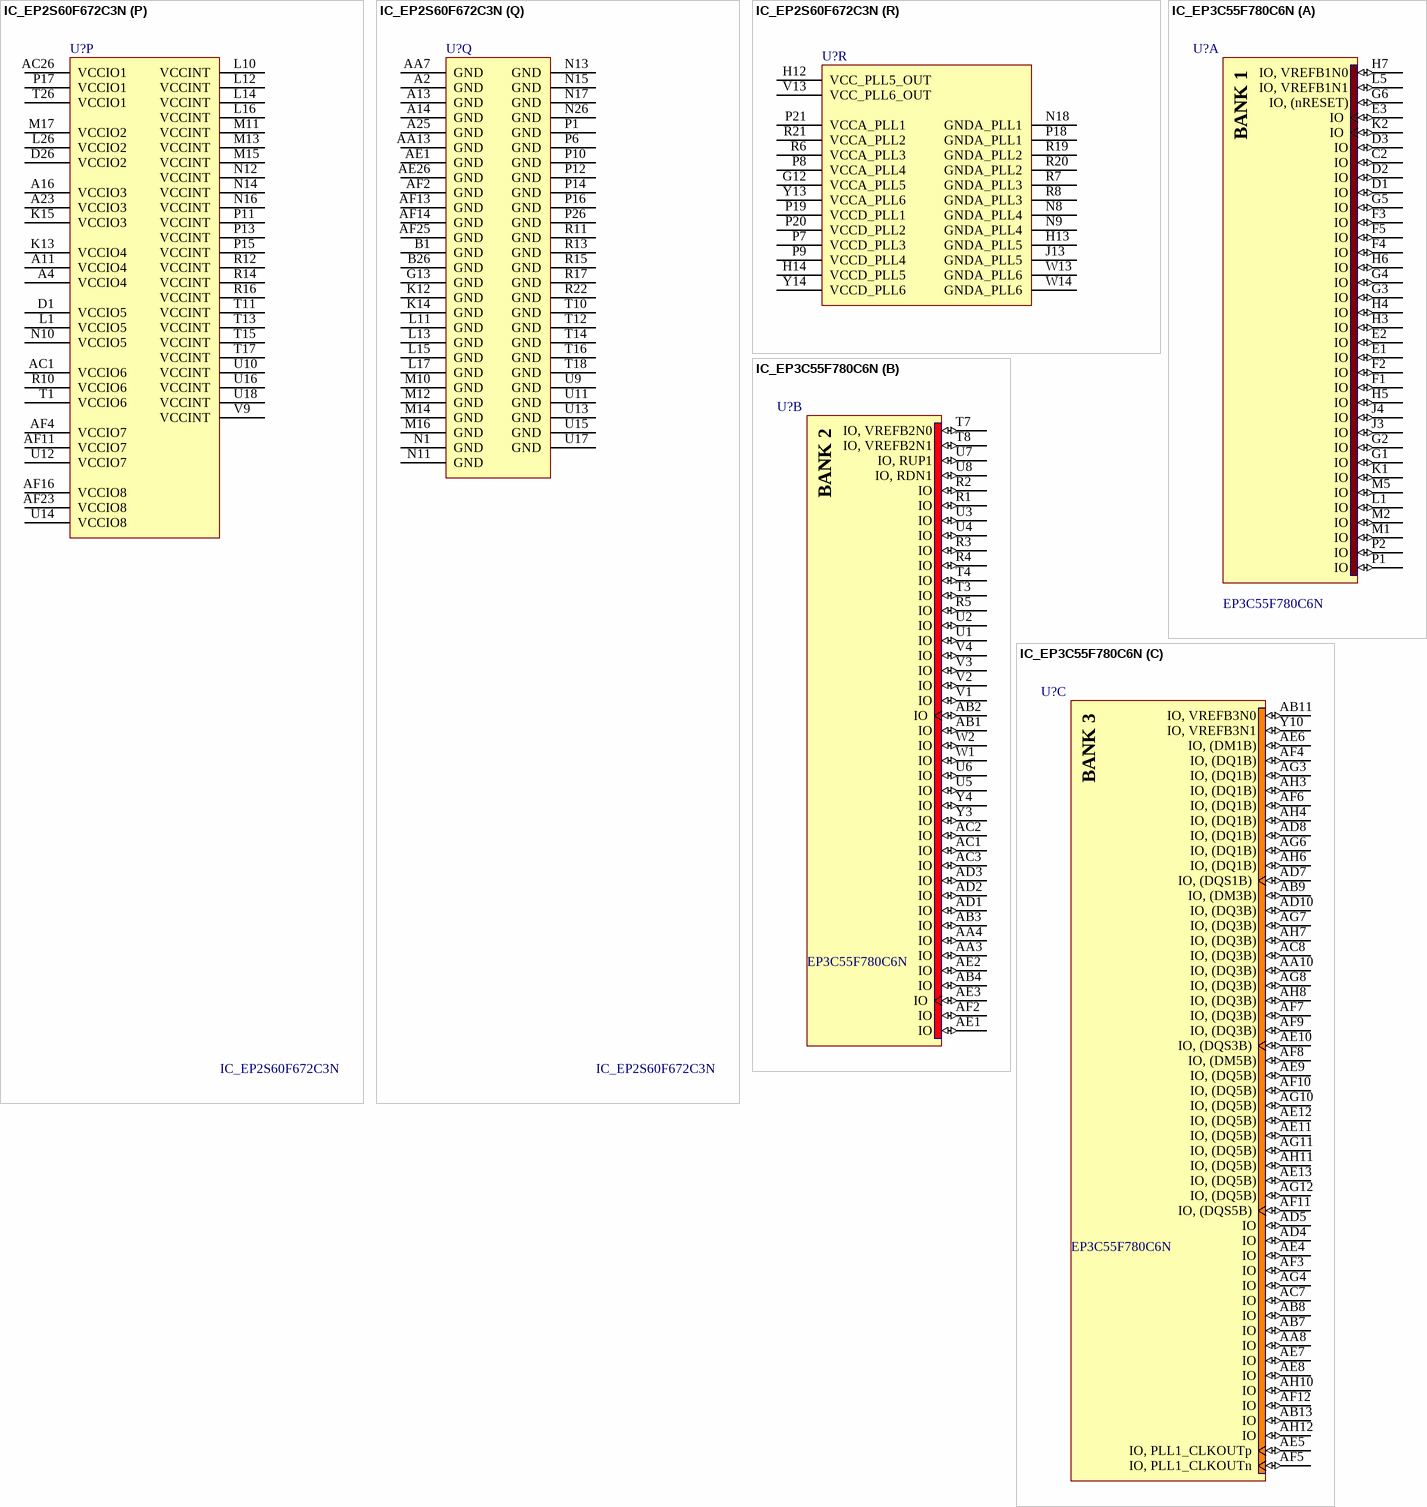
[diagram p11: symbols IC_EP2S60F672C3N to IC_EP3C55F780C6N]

## IC_EP2S60F672C3N
designator U?
Stratix II 1.2V FPGA, 492 I/Os, 672-Pin FineLine BGA, Speed Grade 3, Commercial Grade, Pb-Free; Note: DQS signal pins in banks 3, 4, 7 & 8 named according to DQ bus modes. "/" separates each mode. ie. Mode x4, x8/x9, x16/x18 and x32/x36.
footprint FBGA672 (BGA, 672-Leads, Body 27x27mm, Pitch 1mm)
3D model EP2S60-FBGA672T (672-Ball FineLine Ball Grid Array (FBGA672) - Flip Chip)
signal-integrity model EP2S60F672C3N (EP2S60)
part A pins: AA21 IO (io), AA22 IO (io), AA23 IO (io), AA24 IO (io), AA25 IO (io), AA26 IO (io), AB23 IO (io), AB24 IO (io), AB25 IO (io), AB26 IO (io), AC24 IO (io), AC25 IO (io), AD25 IO (io), AD26 IO (io), R23 IO (io), R24 IO (io), R25 IO, CLK2n (io), R26 IO, CLK2p (io), T19 IO (io), T20 IO (io), T21 IO (io), T22 IO (io), T24 IO (io), T25 IO (io), U19 IO (io), U20 IO (io), U21 IO (io), U22 IO (io), U23 IO (io), U24 IO (io), U25 IO (io), U26 IO (io), V19 IO (io), V20 IO (io), V21 IO (io), V22 IO (io), V23 IO (io), V24 IO (io), V25 IO (io), V26 IO (io), W19 IO (io), W20 IO (io), W21 IO (io), W22 IO (io), W23 IO (io), W24 IO (io), W25 IO (io), W26 IO (io), Y20 IO (io), Y21 IO (io), Y23 IO (io), Y24 IO (io), Y25 IO (io), Y26 IO (io)
part B pins: C25 IO (io), C26 IO (io), D24 IO (io), D25 IO (io), E23 IO (io), E24 IO (io), E25 IO (io), E26 IO (io), F21 IO (io), F22 IO (io), F23 IO (io), F24 IO (io), F25 IO (io), F26 IO (io), G20 IO (io), G21 IO (io), G23 IO (io), G24 IO (io), G25 IO (io), G26 IO (io), H19 IO (io), H20 IO (io), H21 IO (io), H22 IO (io), H23 IO (io), H24 IO (io), H25 IO (io), H26 IO (io), J19 IO (io), J20 IO (io), J21 IO (io), J22 IO (io), J23 IO (io), J24 IO (io), J25 IO (io), J26 IO (io), K19 IO (io), K20 IO (io), K21 IO (io), K22 IO (io), K23 IO (io), K24 IO (io), K25 IO (io), K26 IO (io), L18 IO (io), L19 IO (io), L20 IO (io), L21 IO (io), L22 IO (io), L23 IO (io), L24 IO (io), L25 IO (io), M19 IO (io), M20 IO (io), M21 IO (io), M22 IO (io), M23 IO (io), M24 IO (io), M25 IO (io), M26 IO (io), N19 IO (io), N20 IO (io), N21 IO (io), N22 IO (io), P24 IO, CLK0n (io), P25 IO, CLK0p (io)
part C pins: A15 IO, CLK14p (io), A17 IO (io), A18 IO (io), A19 IO (io), A20 IO (io), A21 IO (io), A22 IO (io), A24 IO (io), B15 IO, CLK14n (io), B16 IO (io), B17 IO (io), B18 IO (io), B19 IO (io), B20 IO (io), B21 IO (io), B22 IO (io), B23 IO (io), B24 IO (io), C15 IO, CLK15p (io), C16 IO (io), C17 IO (io), C18 IO (io), C19 IO (io), C20 IO (io), C21 IO (io), C22 IO (io), C23 IO (io), D15 IO, CLK15n (io), D17 IO (io), D18 IO (io), D19 IO (DATA5) (io), D20 IO (DATA3) (io), D21 IO (INIT_DONE) (io), E14 IO (nCSO) (io), E15 IO (PGM2) (io), E16 IO (DATA0) (io), E17 IO (io), E18 IO (io), E19 IO (DATA2) (io), E20 IO (DATA6) (io), F14 IO (PGM0) (io), F15 IO (PGM1) (io), F16 IO (CRC_ERROR) (io), F17 IO (io), F19 IO (RDYnBSY) (io), F20 IO (DATA7) (io), G14 IO (ASDO) (io), G15 IO (DATA1) (io), G16 IO (io), G17 IO (io), G18 IO (io), G19 IO (DATA4) (io), H15 IO (io), H16 IO (io), H17 IO (io), H18 IO (io), J14 IO (io), J15 IO (io), J17 IO (io), J18 IO (io), K16 IO (io), K17 IO (io), K18 IO (io)
part D pins: A3 IO (io), A5 IO (io), A6 IO (io), A7 IO (io), A8 IO (io), A9 IO (io), A10 IO (io), B3 IO (io), B4 IO (io), B5 IO (io), B6 IO (io), B7 IO (io), B8 IO (io), B9 IO (io), B10 IO (io), B11 IO (io), B13 IO, CLK12p (io), B14 IO, CLK13p (io), C3 IO (io), C4 IO (io), C5 IO (io), C6 IO (io), C7 IO (io), C8 IO (io), C9 IO (io), C10 IO (io), C11 IO (io), C13 IO, CLK12n (io), C14 IO, CLK13n (io), D6 IO (io), D7 IO (io), D8 IO (io), D9 IO (io), D10 IO (io), E7 IO, RUP4 (io), E8 IO, RDN4 (io), E9 IO (io), E10 IO (io), E11 IO (io), E12 IO (io), F8 IO (io), F10 IO (io), F11 IO (io), F12 IO (io), F13 IO (io), G9 IO (io), G10 IO (io), G11 IO (io), H9 IO (io), H10 IO (io), H11 IO (io), J9 IO (io), J10 IO (io), J11 IO (io), K10 IO (io), K11 IO (io)
part E pins: C1 IO (io), C2 IO (io), D2 IO (io), D3 IO (io), E1 IO (io), E2 IO (io), E3 IO (io), E4 IO (io), F1 IO (io), F2 IO (io), F3 IO (io), F4 IO (io), G1 IO (io), G2 IO (io), G3 IO (io), G4 IO (io), G6 IO (io), G7 IO (io), H1 IO (io), H2 IO (io), H3 IO (io), H4 IO (io), H5 IO (io), H6 IO (io), H7 IO (io), H8 IO (io), J1 IO (io), J2 IO (io), J3 IO (io), J4 IO (io), J5 IO (io), J6 IO (io), J7 IO (io), J8 IO (io), K1 IO (io), K2 IO (io), K3 IO (io), K4 IO (io), K6 IO (io), K7 IO (io), K8 IO (io), K9 IO (io), L2 IO (io), L3 IO (io), L4 IO (io), L5 IO (io), L6 IO (io), L7 IO (io), L8 IO (io), L9 IO (io), M1 IO (io), M2 IO (io), M3 IO (io), M4 IO (io), M5 IO (io), M6 IO (io), M7 IO (io), M8 IO (io), N4 IO (io), N5 IO (io), N6 IO (io), N7 IO (io), P2 IO, CLK10p (io), P3 IO, CLK10n (io), P4 IO (io), P5 IO (io)
part F pins: AA1 IO (io), AA2 IO (io), AA3 IO (io), AA4 IO (io), AA5 IO (io), AA6 IO (io), AB1 IO (io), AB2 IO (io), AB3 IO (io), AB4 IO (io), AC2 IO (io), AC3 IO (io), AD1 IO (io), AD2 IO (io), R1 IO, CLK8p (io), R2 IO, CLK8n (io), T2 IO (io), T3 IO (io), T4 IO (io), T5 IO (io), T6 IO (io), T7 IO (io), T8 IO (io), T9 IO (io), U1 IO (io), U2 IO (io), U3 IO (io), U4 IO (io), U5 IO (io), U6 IO (io), U7 IO (io), U8 IO (io), V1 IO (io), V2 IO (io), V3 IO (io), V4 IO (io), V5 IO (io), V6 IO (io), V7 IO (io), V8 IO (io), W1 IO (io), W2 IO (io), W3 IO (io), W4 IO (io), W5 IO (io), W6 IO (io), W7 IO (io), W8 IO (io), Y1 IO (io), Y2 IO (io), Y3 IO (io), Y4 IO (io), Y6 IO (io), Y7 IO (io)
part G pins: AA8 IO (io), AA10 IO (io), AA11 IO (io), AA12 IO (io), AB7 IO (io), AB8 IO (io), AB9 IO, RDN7 (io), AB10 IO, RUP7 (io), AB11 IO (io), AB12 IO (io), AB13 IO, CLK7n (io), AC6 IO (io), AC7 IO (io), AC8 IO (io), AC9 IO (io), AC10 IO (io), AC13 IO, CLK7p (io), AD3 IO (io), AD4 IO (io), AD5 IO (io), AD6 IO (io), AD7 IO (io), AD8 IO (io), AD9 IO (io), AD10 IO (io), AD11 IO (io), AD14 IO, CLK6n (io), AE3 IO (io), AE4 IO (io), AE5 IO (io), AE6 IO (io), AE7 IO (io), AE8 IO (io), AE9 IO (io), AE10 IO (io), AE11 IO (io), AE14 IO, CLK6p (io), AF3 IO (io), AF5 IO (io), AF6 IO (io), AF7 IO (io), AF8 IO (io), AF9 IO (io), AF10 IO (io), V10 IO (io), V12 IO (io), W9 IO (io), W10 IO (io), W11 IO (io), W12 IO (io), Y9 IO (io), Y10 IO (io), Y11 IO (io), Y12 IO (io)
part H pins: AA14 IO (DEV_OE) (io), AA15 IO (DEV_CLRn) (io), AA16 IO (io), AA17 IO (io), AA19 IO (CLKUSR) (io), AB14 IO, CLK5n (io), AB15 IO (nCS) (io), AB16 IO (io), AB17 IO (io), AB18 IO (io), AB19 IO (io), AB20 IO (nWS) (io), AC14 IO, CLK5p (io), AC17 IO (io), AC18 IO (io), AC19 IO (io), AC20 IO (nRS) (io), AC21 IO (CS) (io), AD16 IO (io), AD17 IO (io), AD18 IO (io), AD19 IO (io), AD20 IO (io), AD21 IO (io), AD22 IO (io), AD23 IO (io), AE15 IO, CLK4n (io), AE16 IO (io), AE17 IO (io), AE18 IO (io), AE19 IO (io), AE20 IO (io), AE21 IO (io), AE22 IO (io), AE23 IO (io), AE24 IO (io), AF15 IO, CLK4p (io), AF17 IO (io), AF18 IO (io), AF19 IO (io), AF20 IO (io), AF21 IO (io), AF22 IO (io), AF24 IO (io), V14 IO (io), V16 IO (io), V17 IO (io), V18 IO (io), W15 IO (io), W16 IO (io), W17 IO (io), W18 IO (io), Y15 IO (RUnLU) (io), Y16 IO (io), Y17 IO (io), Y18 IO (io)
part I pins: A12 IO, PLL5_OUT0p (io), B12 IO, PLL5_OUT0n (io), C12 IO, PLL5_FBp/OUT2p (io), D12 IO, PLL5_FBn/OUT2n (io), D13 IO, PLL5_OUT1p (io), E13 IO, PLL5_OUT1n (io)
part J pins: AC12 IO, PLL6_FBn/OUT2n (io), AD12 IO, PLL6_FBp/OUT2p (io), AD13 IO, PLL6_OUT1n (io), AE12 IO, PLL6_OUT0n (io), AE13 IO, PLL6_OUT1p (io), AF12 IO, PLL6_OUT0p (io)
part K pins: D14 IO, PLL11_OUT0n (io)
part L pins: AC15 IO, PLL12_FBn/OUT2n (io), AD15 IO, PLL12_OUT0p (io)
part M pins: N2 CLK11p, INPUT (in), N3 CLK11n, INPUT (in), N24 CLK1n, INPUT (in), N25 CLK1p, INPUT (in), P22 CLK3n, INPUT (in), P23 CLK3p, INPUT (in), R3 CLK9p, INPUT (in), R4 CLK9n, INPUT (in)
part N pins: AA9 VREFB7N1 (in), AA18 VREFB8N1 (in), AC4 VREFB6N0 (in), AC5 VREFB7N2 (in), AC11 VREFB7N0 (in), AC16 VREFB8N2 (in), AC22 VREFB8N0 (in), AC23 VREFB1N2 (in), D4 VREFB5N2 (in), D5 VREFB4N0 (in), D11 VREFB4N2 (in), D16 VREFB3N0 (in), D22 VREFB3N2 (in), D23 VREFB2N0 (in), F9 VREFB4N1 (in), F18 VREFB3N1 (in), G5 VREFB5N1 (in), G22 VREFB2N1 (in), K5 VREFB5N0 (in), N23 VREFB2N2 (in), R5 VREFB6N2 (in), T23 VREFB1N0 (in), Y5 VREFB6N1 (in), Y22 VREFB1N1 (in)
part O pins: AA20 nCONFIG (in), AB5 nCEO (out), AB6 PLL_ENA (in), AB21 TRST (in), AB22 TCK (in), AD24 TMS (in), AE2 nIO_PULLUP (in), AE25 TDI (in), B2 MSEL1 (in), B25 CONF_DONE (io), C24 DCLK (in), E5 TEMPDIODEp (in), E6 MSEL2 (in), E21 nSTATUS (io), E22 nCE (in), F5 TEMPDIODEn (in), F6 TDO (out), F7 MSEL3 (in), G8 MSEL0 (in), J12 VCCPD4 (power), J16 VCCPD3 (power), M9 VCCPD5 (power), M18 VCCPD2 (power), R9 VCCPD6 (power), R18 VCCPD1 (power), V11 VCCPD7 (power), V15 VCCPD8 (power), Y8 PORSEL (in), Y19 VCCSEL (in)
part P pins: A4 VCCIO4 (power), A11 VCCIO4 (power), A16 VCCIO3 (power), A23 VCCIO3 (power), AC1 VCCIO6 (power), AC26 VCCIO1 (power), AF4 VCCIO7 (power), AF11 VCCIO7 (power), AF16 VCCIO8 (power), AF23 VCCIO8 (power), D1 VCCIO5 (power), D26 VCCIO2 (power), K13 VCCIO4 (power), K15 VCCIO3 (power), L1 VCCIO5 (power), L10 VCCINT (power), L12 VCCINT (power), L14 VCCINT (power), L16 VCCINT (power), L26 VCCIO2 (power), M11 VCCINT (power), M13 VCCINT (power), M15 VCCINT (power), M17 VCCIO2 (power), N10 VCCIO5 (power), N12 VCCINT (power), N14 VCCINT (power), N16 VCCINT (power), P11 VCCINT (power), P13 VCCINT (power), P15 VCCINT (power), P17 VCCIO1 (power), R10 VCCIO6 (power), R12 VCCINT (power), R14 VCCINT (power), R16 VCCINT (power), T1 VCCIO6 (power), T11 VCCINT (power), T13 VCCINT (power), T15 VCCINT (power), T17 VCCINT (power), T26 VCCIO1 (power), U10 VCCINT (power), U12 VCCIO7 (power), U14 VCCIO8 (power), U16 VCCINT (power), U18 VCCINT (power), V9 VCCINT (power)
part Q pins: A2 GND (power), A13 GND (power), A14 GND (power), A25 GND (power), AA7 GND (power), AA13 GND (power), AE1 GND (power), AE26 GND (power), AF2 GND (power), AF13 GND (power), AF14 GND (power), AF25 GND (power), B1 GND (power), B26 GND (power), G13 GND (power), K12 GND (power), K14 GND (power), L11 GND (power), L13 GND (power), L15 GND (power), L17 GND (power), M10 GND (power), M12 GND (power), M14 GND (power), M16 GND (power), N1 GND (power), N11 GND (power), N13 GND (power), N15 GND (power), N17 GND (power), N26 GND (power), P1 GND (power), P6 GND (power), P10 GND (power), P12 GND (power), P14 GND (power), P16 GND (power), P26 GND (power), R11 GND (power), R13 GND (power), R15 GND (power), R17 GND (power), R22 GND (power), T10 GND (power), T12 GND (power), T14 GND (power), T16 GND (power), T18 GND (power), U9 GND (power), U11 GND (power), U13 GND (power), U15 GND (power), U17 GND (power)
part R pins: G12 VCCA_PLL5 (power), H12 VCC_PLL5_OUT (power), H13 GNDA_PLL5 (power), H14 VCCD_PLL5 (power), J13 GNDA_PLL5 (power), N8 GNDA_PLL4 (power), N9 GNDA_PLL4 (power), N18 GNDA_PLL1 (power), P7 VCCD_PLL3 (power), P8 VCCA_PLL4 (power), P9 VCCD_PLL4 (power), P18 GNDA_PLL1 (power), P19 VCCD_PLL1 (power), P20 VCCD_PLL2 (power), P21 VCCA_PLL1 (power), R6 VCCA_PLL3 (power), R7 GNDA_PLL3 (power), R8 GNDA_PLL3 (power), R19 GNDA_PLL2 (power), R20 GNDA_PLL2 (power), R21 VCCA_PLL2 (power), V13 VCC_PLL6_OUT (power), W13 GNDA_PLL6 (power), W14 GNDA_PLL6 (power), Y13 VCCA_PLL6 (power), Y14 VCCD_PLL6 (power)

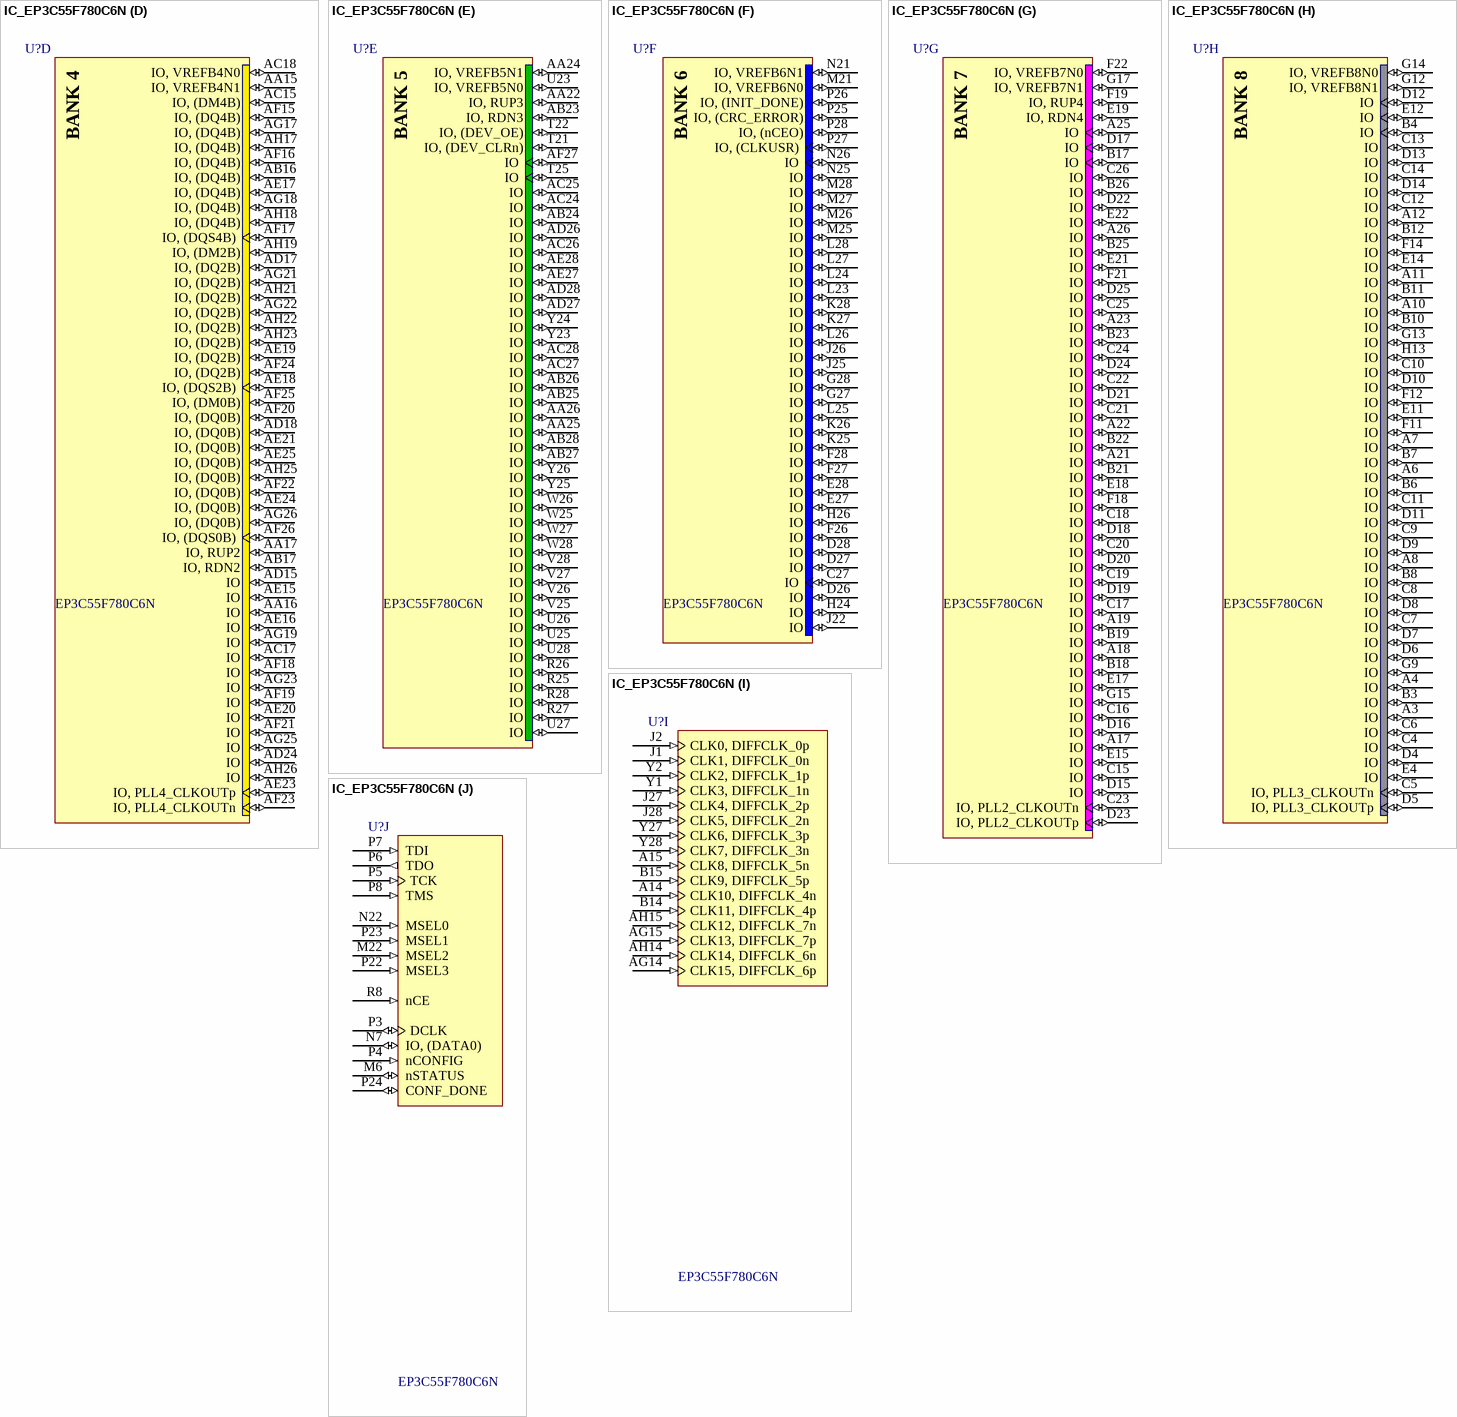
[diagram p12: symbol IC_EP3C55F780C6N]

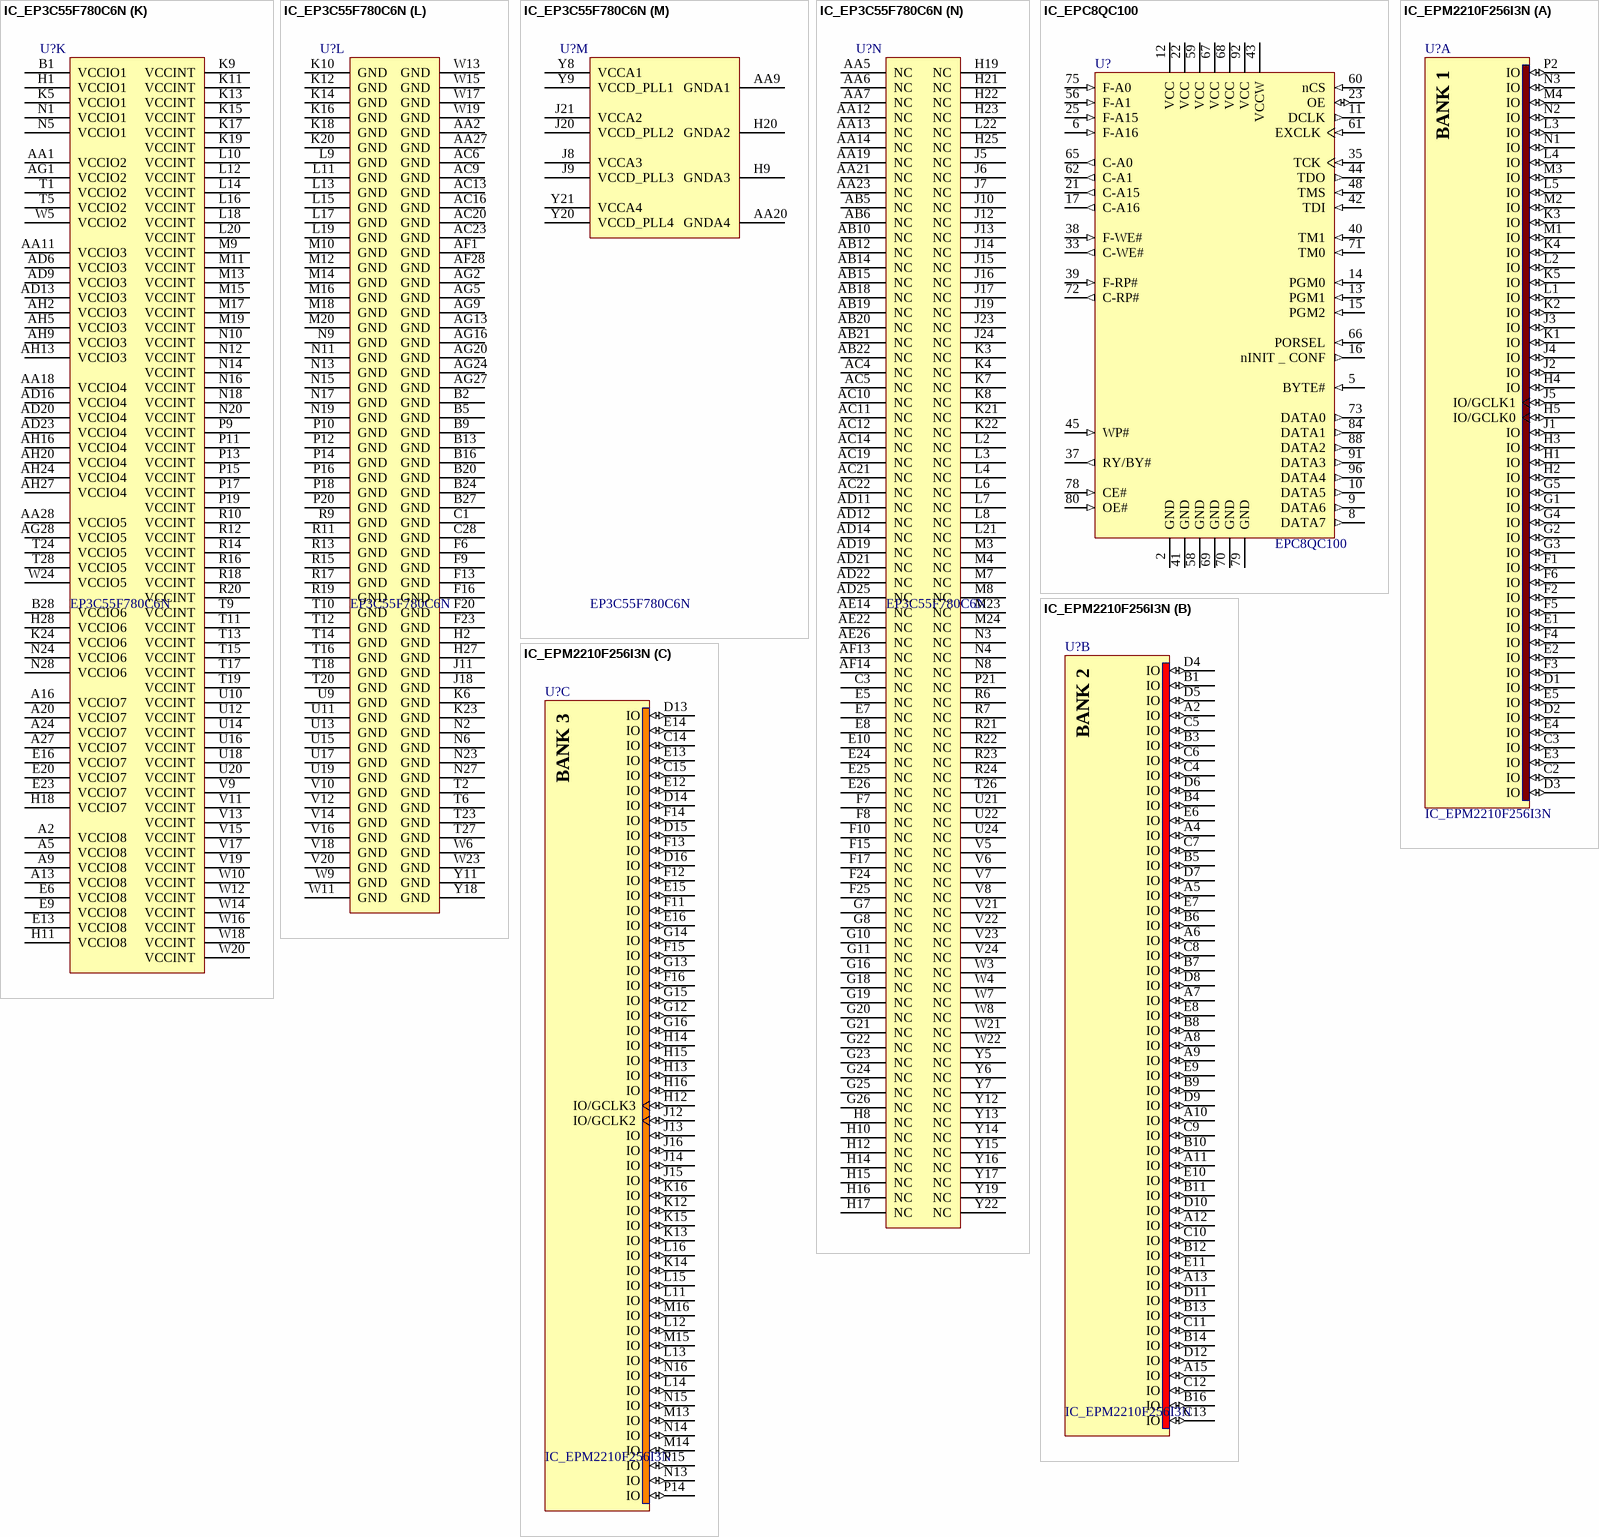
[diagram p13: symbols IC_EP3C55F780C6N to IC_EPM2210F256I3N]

## IC_EP3C55F780C6N
designator U?, comment EP3C55F780C6N
Cyclone III Family FPGA, 377 I/O Pins, 4 PLLs, 780-Pin FBGA, Speed Grade 6, Commercial Grade, Pb-Free
footprint FBGA780-2 (BGA, 780-Leads, Body 29x29mm, Pitch 1mm)
3D model EP3C55-FBGA780-2 (780-Ball FineLine Ball Grid Array (FBGA780) - Option 2 - Wire Bond)
signal-integrity model EP3C55_F780 (Cyclone III)
part A pins: C2 IO (io), D1 IO (io), D2 IO (io), D3 IO (io), E1 IO (io), E2 IO (io), E3 IO (io), F1 IO (io), F2 IO (io), F3 IO (io), F4 IO (io), F5 IO (io), G1 IO (io), G2 IO (io), G3 IO (io), G4 IO (io), G5 IO (io), G6 IO, (nRESET) (io), H3 IO (io), H4 IO (io), H5 IO (io), H6 IO (io), H7 IO, VREFB1N0 (io), J3 IO (io), J4 IO (io), K1 IO (io), K2 IO (io), L1 IO (io), L5 IO, VREFB1N1 (io), M1 IO (io), M2 IO (io), M5 IO (io), P1 IO (io), P2 IO (io)
part B pins: AA3 IO (io), AA4 IO (io), AB1 IO (io), AB2 IO (io), AB3 IO (io), AB4 IO (io), AC1 IO (io), AC2 IO (io), AC3 IO (io), AD1 IO (io), AD2 IO (io), AD3 IO (io), AE1 IO (io), AE2 IO (io), AE3 IO (io), AF2 IO (io), R1 IO (io), R2 IO (io), R3 IO (io), R4 IO (io), R5 IO (io), T3 IO (io), T4 IO (io), T7 IO, VREFB2N0 (io), T8 IO, VREFB2N1 (io), U1 IO (io), U2 IO (io), U3 IO (io), U4 IO (io), U5 IO (io), U6 IO (io), U7 IO, RUP1 (io), U8 IO, RDN1 (io), V1 IO (io), V2 IO (io), V3 IO (io), V4 IO (io), W1 IO (io), W2 IO (io), Y3 IO (io), Y4 IO (io)
part C pins: AA8 IO (io), AA10 IO, (DQ3B) (io), AB7 IO (io), AB8 IO (io), AB9 IO, (DM3B) (io), AB11 IO, VREFB3N0 (io), AB13 IO (io), AC7 IO (io), AC8 IO, (DQ3B) (io), AD4 IO (io), AD5 IO (io), AD7 IO, (DQS1B) (io), AD8 IO, (DQ1B) (io), AD10 IO, (DQ3B) (io), AE4 IO (io), AE5 IO, PLL1_CLKOUTp (io), AE6 IO, (DM1B) (io), AE7 IO (io), AE8 IO (io), AE9 IO, (DQ5B) (io), AE10 IO, (DQS3B) (io), AE11 IO, (DQ5B) (io), AE12 IO, (DQ5B) (io), AE13 IO, (DQ5B) (io), AF3 IO (io), AF4 IO, (DQ1B) (io), AF5 IO, PLL1_CLKOUTn (io), AF6 IO, (DQ1B) (io), AF7 IO, (DQ3B) (io), AF8 IO, (DM5B) (io), AF9 IO, (DQ3B) (io), AF10 IO, (DQ5B) (io), AF11 IO, (DQS5B) (io), AF12 IO (io), AG3 IO, (DQ1B) (io), AG4 IO (io), AG6 IO, (DQ1B) (io), AG7 IO, (DQ3B) (io), AG8 IO, (DQ3B) (io), AG10 IO, (DQ5B) (io), AG11 IO, (DQ5B) (io), AG12 IO, (DQ5B) (io), AH3 IO, (DQ1B) (io), AH4 IO, (DQ1B) (io), AH6 IO, (DQ1B) (io), AH7 IO, (DQ3B) (io), AH8 IO, (DQ3B) (io), AH10 IO (io), AH11 IO, (DQ5B) (io), AH12 IO (io), Y10 IO, VREFB3N1 (io)
part D pins: AA15 IO, VREFB4N1 (io), AA16 IO (io), AA17 IO, RUP2 (io), AB16 IO, (DQ4B) (io), AB17 IO, RDN2 (io), AC15 IO, (DM4B) (io), AC17 IO (io), AC18 IO, VREFB4N0 (io), AD15 IO (io), AD17 IO, (DQ2B) (io), AD18 IO, (DQ0B) (io), AD24 IO (io), AE15 IO (io), AE16 IO (io), AE17 IO, (DQ4B) (io), AE18 IO, (DQS2B) (io), AE19 IO, (DQ2B) (io), AE20 IO (io), AE21 IO, (DQ0B) (io), AE23 IO, PLL4_CLKOUTp (io), AE24 IO, (DQ0B) (io), AE25 IO, (DQ0B) (io), AF15 IO, (DQ4B) (io), AF16 IO, (DQ4B) (io), AF17 IO, (DQS4B) (io), AF18 IO (io), AF19 IO (io), AF20 IO, (DQ0B) (io), AF21 IO (io), AF22 IO, (DQ0B) (io), AF23 IO, PLL4_CLKOUTn (io), AF24 IO, (DQ2B) (io), AF25 IO, (DM0B) (io), AF26 IO, (DQS0B) (io), AG17 IO, (DQ4B) (io), AG18 IO, (DQ4B) (io), AG19 IO (io), AG21 IO, (DQ2B) (io), AG22 IO, (DQ2B) (io), AG23 IO (io), AG25 IO (io), AG26 IO, (DQ0B) (io), AH17 IO, (DQ4B) (io), AH18 IO, (DQ4B) (io), AH19 IO, (DM2B) (io), AH21 IO, (DQ2B) (io), AH22 IO, (DQ2B) (io), AH23 IO, (DQ2B) (io), AH25 IO, (DQ0B) (io), AH26 IO (io)
part E pins: AA22 IO, RUP3 (io), AA24 IO, VREFB5N1 (io), AA25 IO (io), AA26 IO (io), AB23 IO, RDN3 (io), AB24 IO (io), AB25 IO (io), AB26 IO (io), AB27 IO (io), AB28 IO (io), AC24 IO (io), AC25 IO (io), AC26 IO (io), AC27 IO (io), AC28 IO (io), AD26 IO (io), AD27 IO (io), AD28 IO (io), AE27 IO (io), AE28 IO (io), AF27 IO (io), R25 IO (io), R26 IO (io), R27 IO (io), R28 IO (io), T21 IO, (DEV_CLRn) (io), T22 IO, (DEV_OE) (io), T25 IO (io), U23 IO, VREFB5N0 (io), U25 IO (io), U26 IO (io), U27 IO (io), U28 IO (io), V25 IO (io), V26 IO (io), V27 IO (io), V28 IO (io), W25 IO (io), W26 IO (io), W27 IO (io), W28 IO (io), Y23 IO (io), Y24 IO (io), Y25 IO (io), Y26 IO (io)
part F pins: C27 IO (io), D26 IO (io), D27 IO (io), D28 IO (io), E27 IO (io), E28 IO (io), F26 IO (io), F27 IO (io), F28 IO (io), G27 IO (io), G28 IO (io), H24 IO (io), H26 IO (io), J22 IO (io), J25 IO (io), J26 IO (io), K25 IO (io), K26 IO (io), K27 IO (io), K28 IO (io), L23 IO (io), L24 IO (io), L25 IO (io), L26 IO (io), L27 IO (io), L28 IO (io), M21 IO, VREFB6N0 (io), M25 IO (io), M26 IO (io), M27 IO (io), M28 IO (io), N21 IO, VREFB6N1 (io), N25 IO (io), N26 IO (io), P25 IO, (CRC_ERROR) (io), P26 IO, (INIT_DONE) (io), P27 IO, (CLKUSR) (io), P28 IO, (nCEO) (io)
part G pins: A17 IO (io), A18 IO (io), A19 IO (io), A21 IO (io), A22 IO (io), A23 IO (io), A25 IO (io), A26 IO (io), B17 IO (io), B18 IO (io), B19 IO (io), B21 IO (io), B22 IO (io), B23 IO (io), B25 IO (io), B26 IO (io), C15 IO (io), C16 IO (io), C17 IO (io), C18 IO (io), C19 IO (io), C20 IO (io), C21 IO (io), C22 IO (io), C23 IO, PLL2_CLKOUTn (io), C24 IO (io), C25 IO (io), C26 IO (io), D15 IO (io), D16 IO (io), D17 IO (io), D18 IO (io), D19 IO (io), D20 IO (io), D21 IO (io), D22 IO (io), D23 IO, PLL2_CLKOUTp (io), D24 IO (io), D25 IO (io), E15 IO (io), E17 IO (io), E18 IO (io), E19 IO, RDN4 (io), E21 IO (io), E22 IO (io), F18 IO (io), F19 IO, RUP4 (io), F21 IO (io), F22 IO, VREFB7N0 (io), G15 IO (io), G17 IO, VREFB7N1 (io)
part H pins: A3 IO (io), A4 IO (io), A6 IO (io), A7 IO (io), A8 IO (io), A10 IO (io), A11 IO (io), A12 IO (io), B3 IO (io), B4 IO (io), B6 IO (io), B7 IO (io), B8 IO (io), B10 IO (io), B11 IO (io), B12 IO (io), C4 IO (io), C5 IO, PLL3_CLKOUTn (io), C6 IO (io), C7 IO (io), C8 IO (io), C9 IO (io), C10 IO (io), C11 IO (io), C12 IO (io), C13 IO (io), C14 IO (io), D4 IO (io), D5 IO, PLL3_CLKOUTp (io), D6 IO (io), D7 IO (io), D8 IO (io), D9 IO (io), D10 IO (io), D11 IO (io), D12 IO (io), D13 IO (io), D14 IO (io), E4 IO (io), E11 IO (io), E12 IO (io), E14 IO (io), F11 IO (io), F12 IO (io), F14 IO (io), G9 IO (io), G12 IO, VREFB8N1 (io), G13 IO (io), G14 IO, VREFB8N0 (io), H13 IO (io)
part I pins: A14 CLK10, DIFFCLK_4n (in), A15 CLK8, DIFFCLK_5n (in), AG14 CLK15, DIFFCLK_6p (in), AG15 CLK13, DIFFCLK_7p (in), AH14 CLK14, DIFFCLK_6n (in), AH15 CLK12, DIFFCLK_7n (in), B14 CLK11, DIFFCLK_4p (in), B15 CLK9, DIFFCLK_5p (in), J1 CLK1, DIFFCLK_0n (in), J2 CLK0, DIFFCLK_0p (in), J27 CLK4, DIFFCLK_2p (in), J28 CLK5, DIFFCLK_2n (in), Y1 CLK3, DIFFCLK_1n (in), Y2 CLK2, DIFFCLK_1p (in), Y27 CLK6, DIFFCLK_3p (in), Y28 CLK7, DIFFCLK_3n (in)
part J pins: M6 nSTATUS (io), M22 MSEL2 (in), N7 IO, (DATA0) (io), N22 MSEL0 (in), P3 DCLK (io), P4 nCONFIG (in), P5 TCK (in), P6 TDO (out), P7 TDI (in), P8 TMS (in), P22 MSEL3 (in), P23 MSEL1 (in), P24 CONF_DONE (io), R8 nCE (in)
part K pins: A2 VCCIO8 (power), A5 VCCIO8 (power), A9 VCCIO8 (power), A13 VCCIO8 (power), A16 VCCIO7 (power), A20 VCCIO7 (power), A24 VCCIO7 (power), A27 VCCIO7 (power), AA1 VCCIO2 (power), AA11 VCCIO3 (power), AA18 VCCIO4 (power), AA28 VCCIO5 (power), AD6 VCCIO3 (power), AD9 VCCIO3 (power), AD13 VCCIO3 (power), AD16 VCCIO4 (power), AD20 VCCIO4 (power), AD23 VCCIO4 (power), AG1 VCCIO2 (power), AG28 VCCIO5 (power), AH2 VCCIO3 (power), AH5 VCCIO3 (power), AH9 VCCIO3 (power), AH13 VCCIO3 (power), AH16 VCCIO4 (power), AH20 VCCIO4 (power), AH24 VCCIO4 (power), AH27 VCCIO4 (power), B1 VCCIO1 (power), B28 VCCIO6 (power), E6 VCCIO8 (power), E9 VCCIO8 (power), E13 VCCIO8 (power), E16 VCCIO7 (power), E20 VCCIO7 (power), E23 VCCIO7 (power), H1 VCCIO1 (power), H11 VCCIO8 (power), H18 VCCIO7 (power), H28 VCCIO6 (power), K5 VCCIO1 (power), K9 VCCINT (power), K11 VCCINT (power), K13 VCCINT (power), K15 VCCINT (power), K17 VCCINT (power), K19 VCCINT (power), K24 VCCIO6 (power), L10 VCCINT (power), L12 VCCINT (power), L14 VCCINT (power), L16 VCCINT (power), L18 VCCINT (power), L20 VCCINT (power), M9 VCCINT (power), M11 VCCINT (power), M13 VCCINT (power), M15 VCCINT (power), M17 VCCINT (power), M19 VCCINT (power), N1 VCCIO1 (power), N5 VCCIO1 (power), N10 VCCINT (power), N12 VCCINT (power), N14 VCCINT (power), N16 VCCINT (power), N18 VCCINT (power), N20 VCCINT (power), N24 VCCIO6 (power), N28 VCCIO6 (power), P9 VCCINT (power), P11 VCCINT (power), P13 VCCINT (power), P15 VCCINT (power), P17 VCCINT (power), P19 VCCINT (power), R10 VCCINT (power), R12 VCCINT (power), R14 VCCINT (power), R16 VCCINT (power), R18 VCCINT (power), R20 VCCINT (power), T1 VCCIO2 (power), T5 VCCIO2 (power), T9 VCCINT (power), T11 VCCINT (power), T13 VCCINT (power), T15 VCCINT (power), T17 VCCINT (power), T19 VCCINT (power), T24 VCCIO5 (power), T28 VCCIO5 (power), U10 VCCINT (power), U12 VCCINT (power), U14 VCCINT (power), U16 VCCINT (power), U18 VCCINT (power), U20 VCCINT (power), V9 VCCINT (power), V11 VCCINT (power), V13 VCCINT (power), V15 VCCINT (power), V17 VCCINT (power), V19 VCCINT (power), W5 VCCIO2 (power), W10 VCCINT (power), W12 VCCINT (power), W14 VCCINT (power), W16 VCCINT (power), W18 VCCINT (power), W20 VCCINT (power), W24 VCCIO5 (power)
part L pins: AA2 GND (power), AA27 GND (power), AC6 GND (power), AC9 GND (power), AC13 GND (power), AC16 GND (power), AC20 GND (power), AC23 GND (power), AF1 GND (power), AF28 GND (power), AG2 GND (power), AG5 GND (power), AG9 GND (power), AG13 GND (power), AG16 GND (power), AG20 GND (power), AG24 GND (power), AG27 GND (power), B2 GND (power), B5 GND (power), B9 GND (power), B13 GND (power), B16 GND (power), B20 GND (power), B24 GND (power), B27 GND (power), C1 GND (power), C28 GND (power), F6 GND (power), F9 GND (power), F13 GND (power), F16 GND (power), F20 GND (power), F23 GND (power), H2 GND (power), H27 GND (power), J11 GND (power), J18 GND (power), K6 GND (power), K10 GND (power), K12 GND (power), K14 GND (power), K16 GND (power), K18 GND (power), K20 GND (power), K23 GND (power), L9 GND (power), L11 GND (power), L13 GND (power), L15 GND (power), L17 GND (power), L19 GND (power), M10 GND (power), M12 GND (power), M14 GND (power), M16 GND (power), M18 GND (power), M20 GND (power), N2 GND (power), N6 GND (power), N9 GND (power), N11 GND (power), N13 GND (power), N15 GND (power), N17 GND (power), N19 GND (power), N23 GND (power), N27 GND (power), P10 GND (power), P12 GND (power), P14 GND (power), P16 GND (power), P18 GND (power), P20 GND (power), R9 GND (power), R11 GND (power), R13 GND (power), R15 GND (power), R17 GND (power), R19 GND (power), T2 GND (power), T6 GND (power), T10 GND (power), T12 GND (power), T14 GND (power), T16 GND (power), T18 GND (power), T20 GND (power), T23 GND (power), T27 GND (power), U9 GND (power), U11 GND (power), U13 GND (power), U15 GND (power), U17 GND (power), U19 GND (power), V10 GND (power), V12 GND (power), V14 GND (power), V16 GND (power), V18 GND (power), V20 GND (power), W6 GND (power), W9 GND (power), W11 GND (power), W13 GND (power), W15 GND (power), W17 GND (power), W19 GND (power), W23 GND (power), Y11 GND (power), Y18 GND (power)
part M pins: AA9 GNDA1 (power), AA20 GNDA4 (power), H9 GNDA3 (power), H20 GNDA2 (power), J8 VCCA3 (power), J9 VCCD_PLL3 (power), J20 VCCD_PLL2 (power), J21 VCCA2 (power), Y8 VCCA1 (power), Y9 VCCD_PLL1 (power), Y20 VCCD_PLL4 (power), Y21 VCCA4 (power)
part N pins: AA5 NC, AA6 NC, AA7 NC, AA12 NC, AA13 NC, AA14 NC, AA19 NC, AA21 NC, AA23 NC, AB5 NC, AB6 NC, AB10 NC, AB12 NC, AB14 NC, AB15 NC, AB18 NC, AB19 NC, AB20 NC, AB21 NC, AB22 NC, AC4 NC, AC5 NC, AC10 NC, AC11 NC, AC12 NC, AC14 NC, AC19 NC, AC21 NC, AC22 NC, AD11 NC, AD12 NC, AD14 NC, AD19 NC, AD21 NC, AD22 NC, AD25 NC, AE14 NC, AE22 NC, AE26 NC, AF13 NC, AF14 NC, C3 NC, E5 NC, E7 NC, E8 NC, E10 NC, E24 NC, E25 NC, E26 NC, F7 NC, F8 NC, F10 NC, F15 NC, F17 NC, F24 NC, F25 NC, G7 NC, G8 NC, G10 NC, G11 NC, G16 NC, G18 NC, G19 NC, G20 NC, G21 NC, G22 NC, G23 NC, G24 NC, G25 NC, G26 NC, H8 NC, H10 NC, H12 NC, H14 NC, H15 NC, H16 NC, H17 NC, H19 NC, H21 NC, H22 NC, H23 NC, H25 NC, J5 NC, J6 NC, J7 NC, J10 NC, J12 NC, J13 NC, J14 NC, J15 NC, J16 NC, J17 NC, J19 NC, J23 NC, J24 NC, K3 NC, K4 NC, K7 NC, K8 NC, K21 NC, K22 NC, L2 NC, L3 NC, L4 NC, L6 NC, L7 NC, L8 NC, L21 NC, L22 NC, M3 NC, M4 NC, M7 NC, M8 NC, M23 NC, M24 NC, N3 NC, N4 NC, N8 NC, P21 NC, R6 NC, R7 NC, R21 NC, R22 NC, R23 NC, R24 NC, T26 NC, U21 NC, U22 NC, U24 NC, V5 NC, V6 NC, V7 NC, V8 NC, V21 NC, V22 NC, V23 NC, V24 NC, W3 NC, W4 NC, W7 NC, W8 NC, W21 NC, W22 NC, Y5 NC, Y6 NC, Y7 NC, Y12 NC, Y13 NC, Y14 NC, Y15 NC, Y16 NC, Y17 NC, Y19 NC, Y22 NC

## IC_EPC8QC100
designator U?, comment EPC8QC100
EPC8 Series, In-system programmable 3.3V configuration device, 100-Pin PQFP, 8-Megabit, Commercial Grade
footprint PQFP100_N (QFP, 100-Leads, Body 20x14mm, Pitch 0.65mm, IPC Medium Density)
3D model EPC8-PQFP100 (100-Pin Plastic Quad Flat Pack (PFQP100) - Option 1)
pins: 1 DQ15 (io) hidden "Data bus that interfaces with flash memory and the controller.", 2 GND (power) "Ground pin", 3 NC hidden "No Connect pin", 4 NC hidden "No Connect pin", 5 BYTE# (in) "Flash byte enable. Connected to VCC.", 6 F-A16 (in) "Address input to flash memory. Should be connected to C-A16 on the board.", 7 Floating hidden "Unconnected pin", 8 DATA7 (out) "PLD configuration output data bus.", 9 DATA6 (out) "PLD configuration output data bus.", 10 DATA5 (out) "PLD configuration output data bus.", 11 DCLK (out) "Configuration devices drive this signal to the programmable logic device (PLD) as a configuration clock.", 12 VCC (power) "Power supply pin", 13 PGM1 (in) "Select one of eight pages that contains configuration data.", 14 PGM0 (in) "Select one of eight pages that contains configuration data.", 15 PGM2 (in) "Select one of eight pages that contains configuration data.", 16 nINIT _ CONF (out) "Initiate configuration.", 17 C-A16 (out) "Address input to flash memory. Should be connected to F-A16 on the board.", 18 NC hidden "No Connect pin", 19 NC hidden "No Connect pin", 20 NC hidden "No Connect pin", 21 C-A15 (out) "Address input to flash memory. Should be connected to F-A15 on the board.", 22 VCC (power) "Power supply pin", 23 OE (io) "Configuration devices sense that OE goes high, before starting PLD configuration.", 24 Floating hidden "Unconnected pin", 25 F-A15 (in) "Address input to flash memory. Should be connected to C-A15 on the board.", 26 A14 (in) hidden "Address input to flash memory.", 27 A13 (in) hidden "Address input to flash memory.", 28 A12 (in) hidden "Address input to flash memory.", 29 A11 (in) hidden "Address input to flash memory.", 30 NC hidden "No Connect pin", 31 A10 (in) hidden "Address input to flash memory.", 32 A9 (in) hidden "Address input to flash memory.", 33 C-WE# (out) "Controller write enable pin. Should be connected to F-WE# on the board", 34 A8 (in) hidden "Address input to flash memory.", 35 TCK (in) "JTAG clock.", 36 A20 (in) hidden "Address input to flash memory.", 37 RY/BY# (out) "Flash ready busy pin. Will be asserted when write or erase operation is completed.", 38 F-WE# (in) "Flash write enable pin. Should be connected to C-WE# on the board", 39 F-RP# (in) "Flash pin which resets the flash memory. Should be connected to C-RP# on the board.", 40 TM1 (in) "Select test mode for configuration device.", 41 GND (power) "Ground pin", 42 TDI (in) "Joint Test Action Group (JTAG) data input.", 43 VCCW (power) "Flash program/erase power supply.", 44 TDO (out) "JTAG data output.", 45 WP# (in) "Flash pin which should be tied to VCC or GND on the board.", 46 A19 (in) hidden "Address input to flash memory.", 47 A18 (in) hidden "Address input to flash memory.", 48 TMS (in) "JTAG mode selection.", 49 A17 (in) hidden "Address input to flash memory.", 50 A7 (in) hidden "Address input to flash memory.", 51 A6 (in) hidden "Address input to flash memory.", 52 A5 (in) hidden "Address input to flash memory.", 53 A4 (in) hidden "Address input to flash memory.", 54 A3 (in) hidden "Address input to flash memory.", 55 A2 (in) hidden "Address input to flash memory.", 56 F-A1 (in) "Address input to flash memory. Should be connected to C-A1 on the board.", 57 Floating hidden "Unconnected pin", 58 GND (power) "Ground pin", 59 VCC (power) "Power supply pin", 60 nCS (in) "Connected to CONF_DONE in the PLD. The PLD will drive it low, when OE is asserted.", 61 EXCLK (in) "External clock source.", 62 C-A1 (out) "Address input to flash memory. Should be connected to F-A1 on the board.", 63 NC hidden "No Connect pin", 64 NC hidden "No Connect pin", 65 C-A0 (out) "Address input to flash memory. Should be connected to F-A0 on the board.", 66 PORSEL (in) "Select 2 ms or 100 ms power-on reset (POR).", 67 VCC (power) "Power supply pin", 68 VCC (power) "Power supply pin", 69 GND (power) "Ground pin", 70 GND (power) "Ground pin", 71 TM0 (in) "Select test mode for configuration device.", 72 C-RP# (out) "Flash pin which resets the flash memory. Should be connected to F-RP# on the board.", 73 DATA0 (out) "PLD configuration output data bus.", 74 Floating hidden "Unconnected pin", 75 F-A0 (in) "Address input to Flash memory. Should be connected to C-A0 on the board.", 76 NC hidden "No Connect pin", 77 NC hidden "No Connect pin", 78 CE# (in) "Flash pin that activates the flash memory.", 79 GND (power) "Ground pin", 80 OE# (in) "Flash pin that enables the drivers of the flash output pins.", 81 DQ0 (io) hidden "Data bus that interfaces with flash memory and the controller.", 82 DQ8 (io) hidden "Data bus that interfaces with flash memory and the controller.", 83 DQ1 (io) hidden "Data bus that interfaces with flash memory and the controller.", 84 DATA1 (out) "PLD configuration output data bus.", 85 DQ9 (io) hidden "Data bus that interfaces with flash memory and the controller.", 86 DQ2 (io) hidden "Data bus that interfaces with flash memory and the controller.", 87 DQ10 (io) hidden "Data bus that interfaces with flash memory and the controller.", 88 DATA2 (out) "PLD configuration output data bus.", 89 DQ3 (io) hidden "Data bus that interfaces with flash memory and the controller.", 90 DQ11 (io) hidden "Data bus that interfaces with flash memory and the controller.", 91 DATA3 (out) "PLD configuration output data bus.", 92 VCC (power) "Power supply pin", 93 DQ4 (io) hidden "Data bus that interfaces with flash memory and the controller.", 94 DQ12 (io) hidden "Data bus that interfaces with flash memory and the controller.", 95 DQ5 (io) hidden "Data bus that interfaces with flash memory and the controller.", 96 DATA4 (out) "PLD configuration output data bus.", 97 DQ13 (io) hidden "Data bus that interfaces with flash memory and the controller.", 98 DQ6 (io) hidden "Data bus that interfaces with flash memory and the controller.", 99 DQ14 (io) hidden "Data bus that interfaces with flash memory and the controller.", 100 DQ7 (io) hidden "Data bus that interfaces with flash memory and the controller."

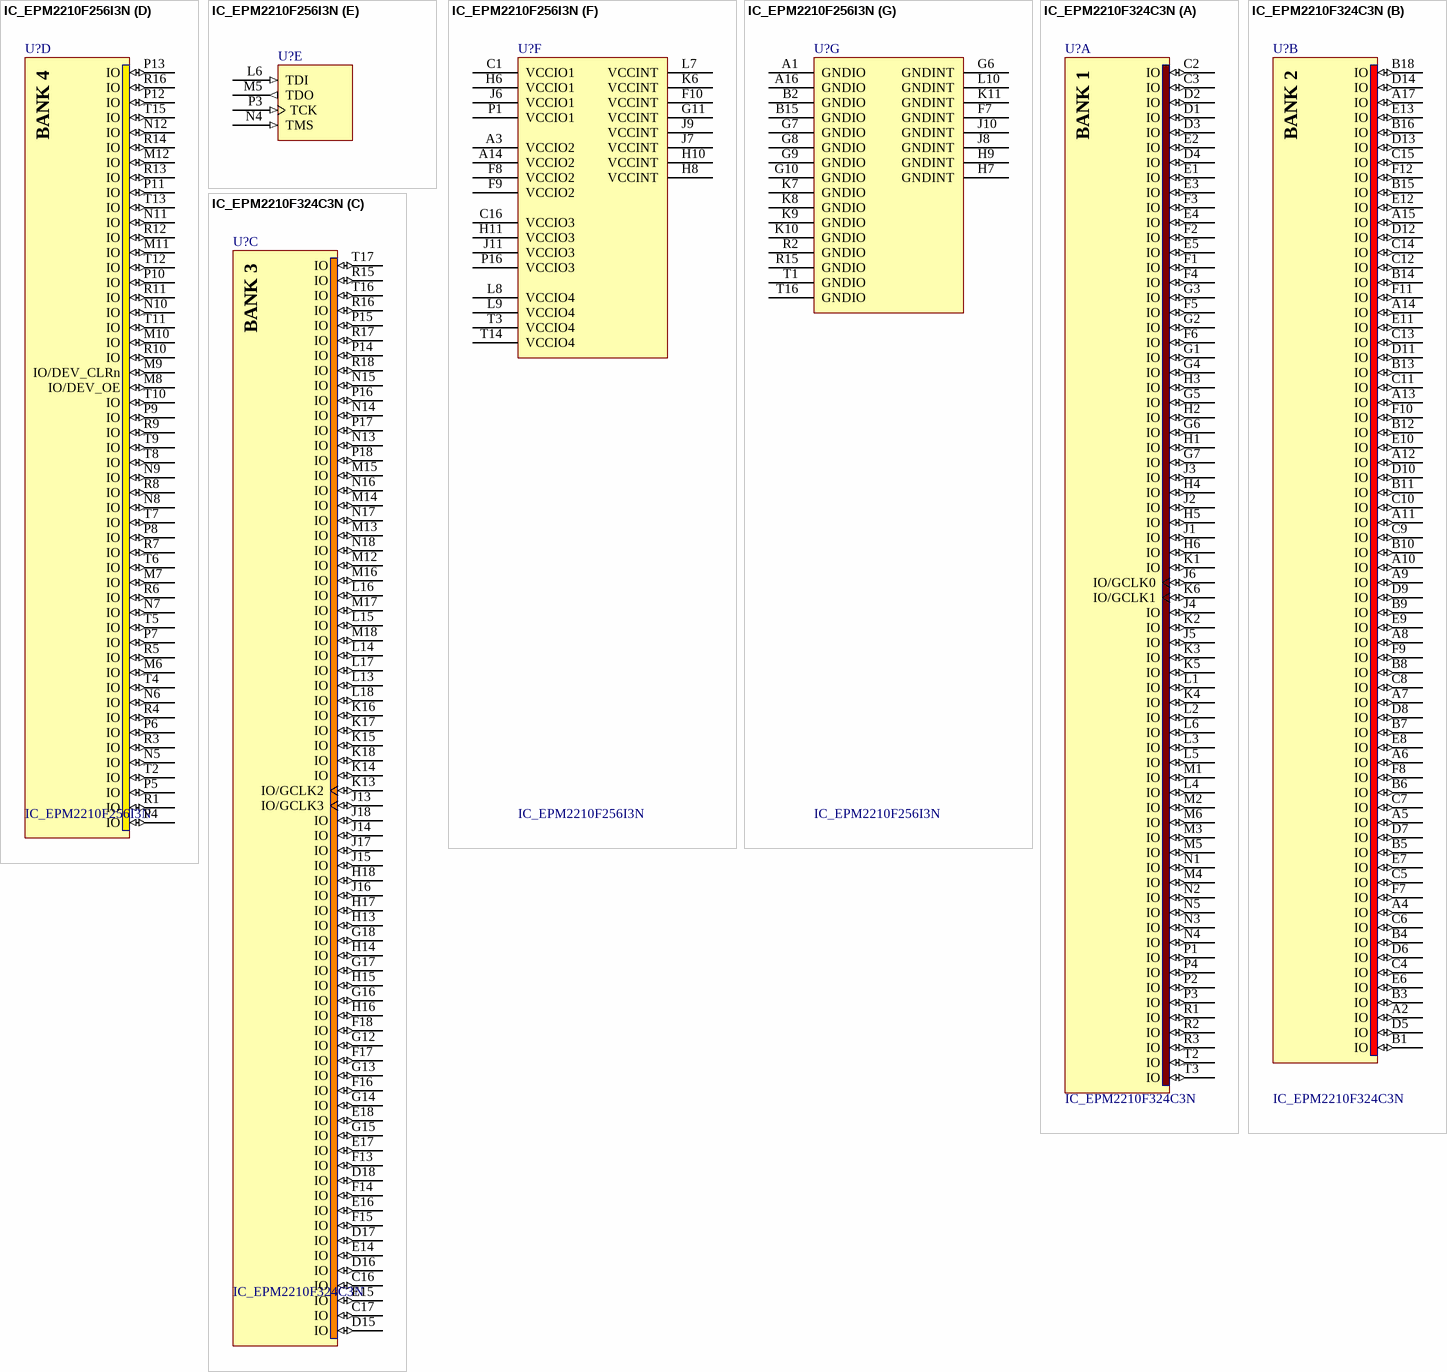
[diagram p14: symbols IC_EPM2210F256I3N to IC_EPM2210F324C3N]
